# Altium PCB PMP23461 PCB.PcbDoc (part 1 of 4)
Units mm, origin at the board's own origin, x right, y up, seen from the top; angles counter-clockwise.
Board outline 240.04 x 159.92 mm, 6 copper layers (Layer 1, Layer 2, Layer 3, Layer 4, Layer 5, Layer 6), stack 2.017 mm thick; 241 components, 120 nets, 654 pads, 744 vias.
Unrouted connection lines stored in the file: 3.
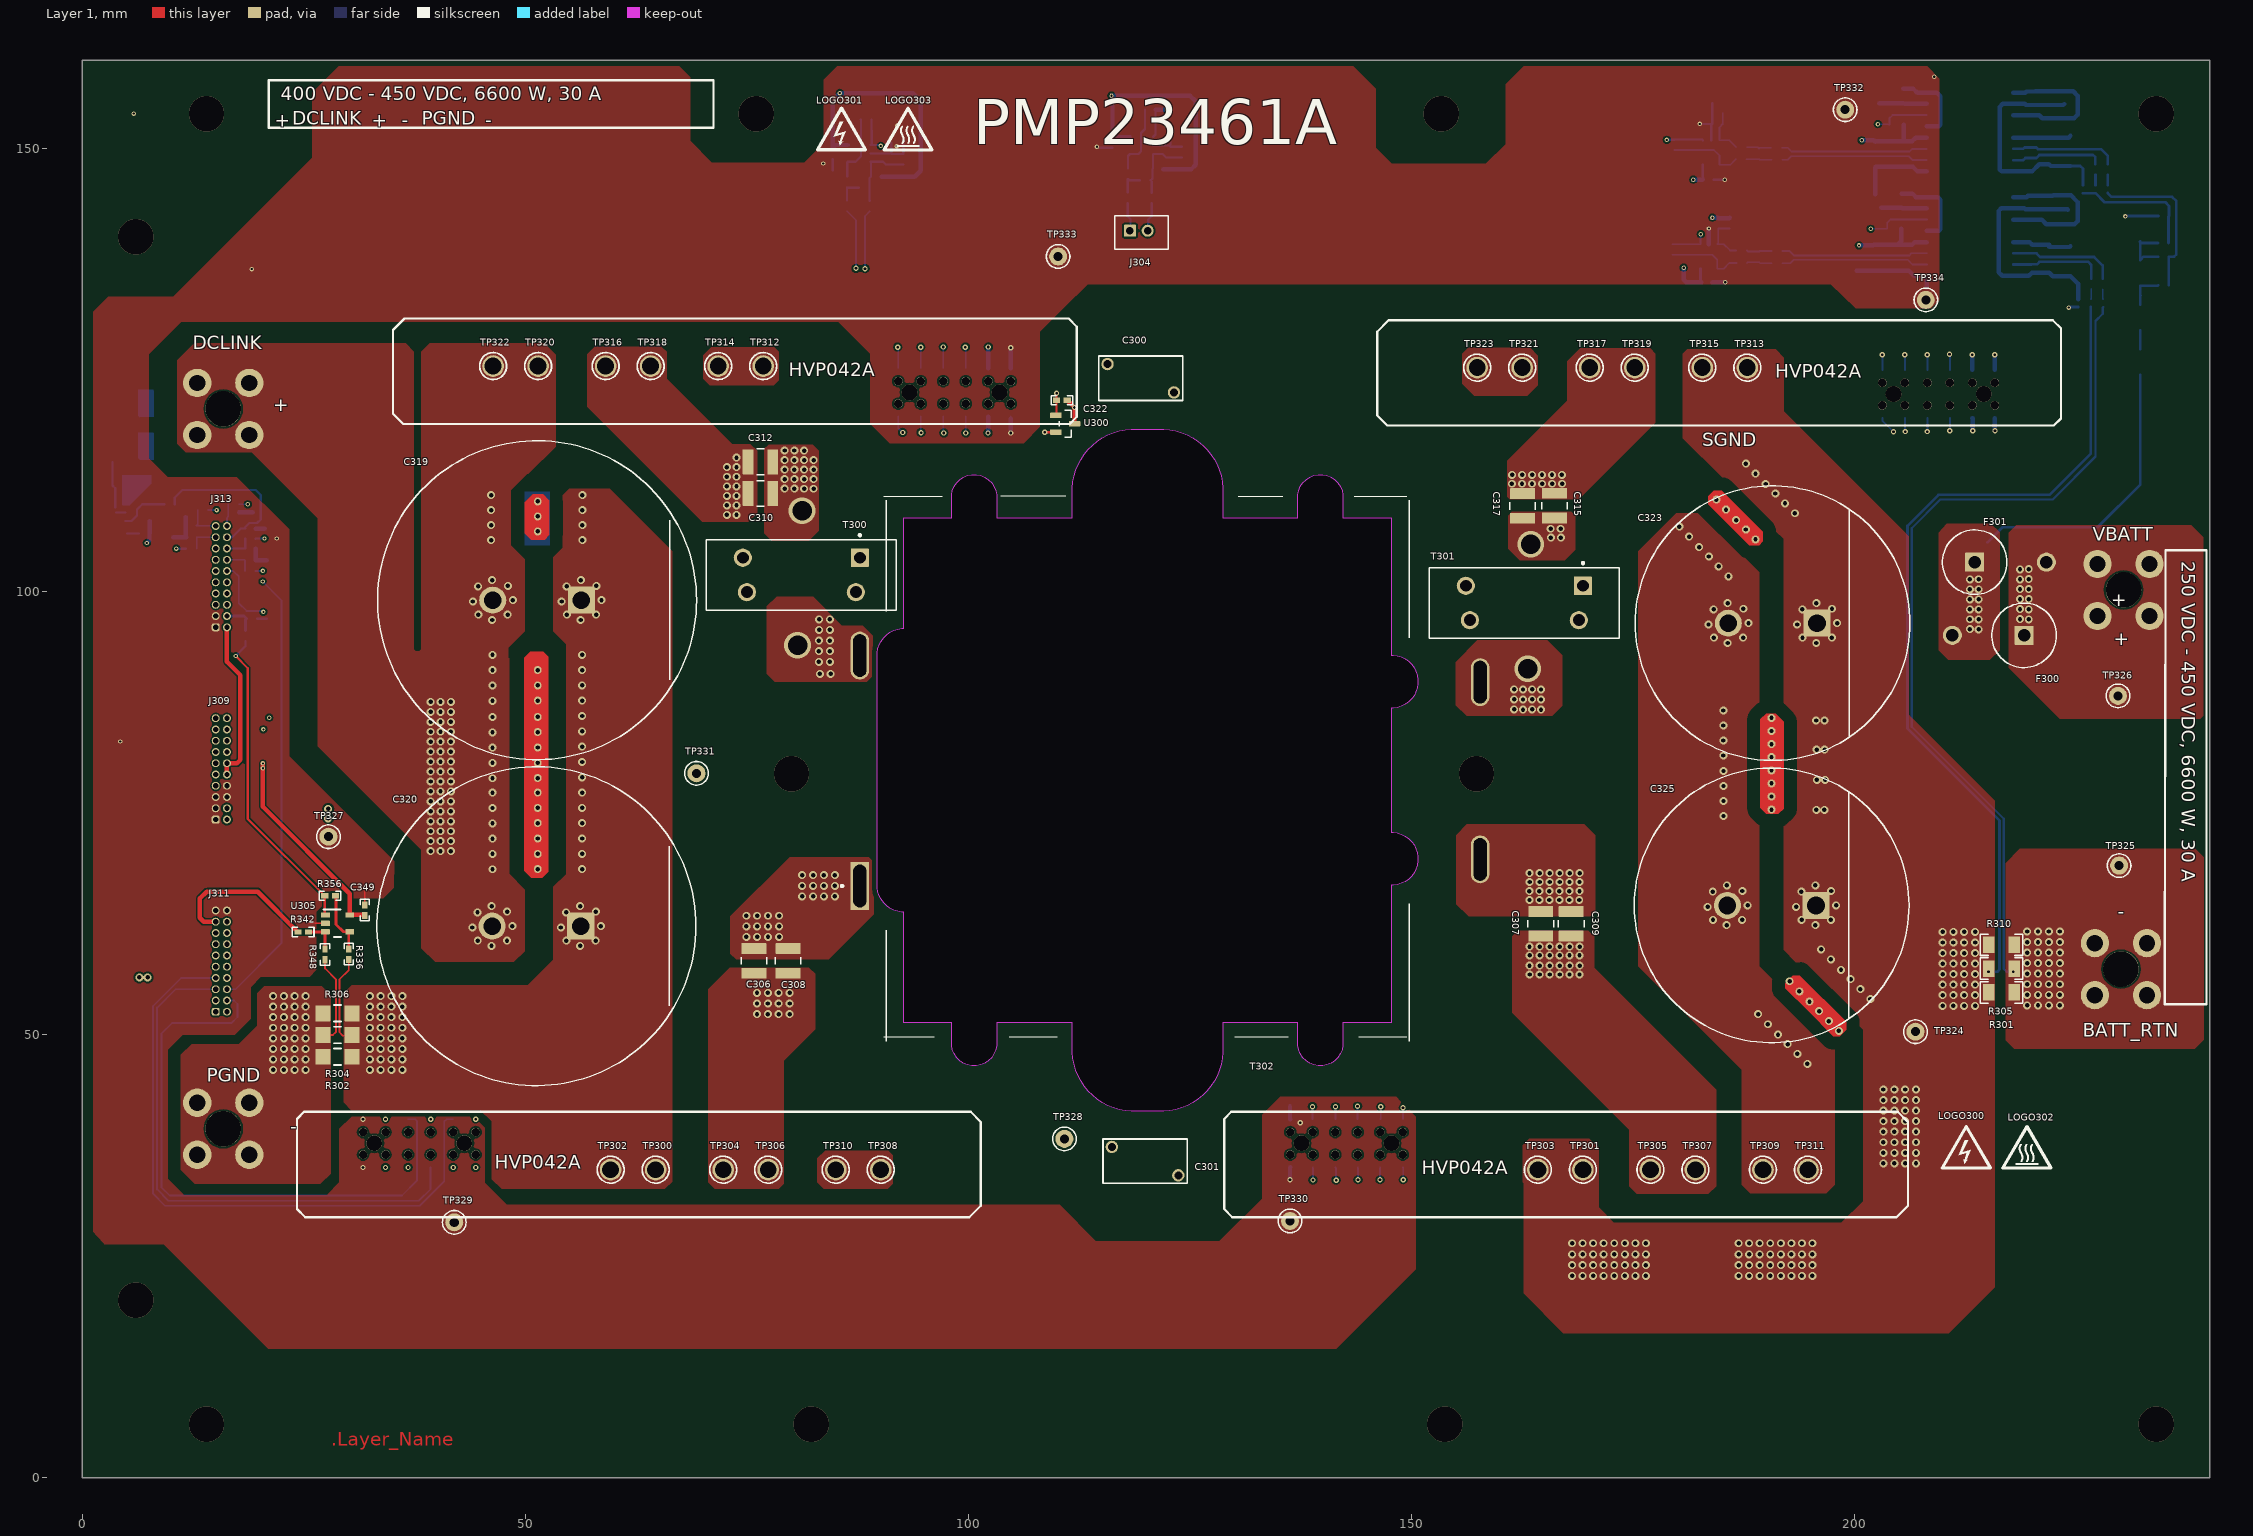
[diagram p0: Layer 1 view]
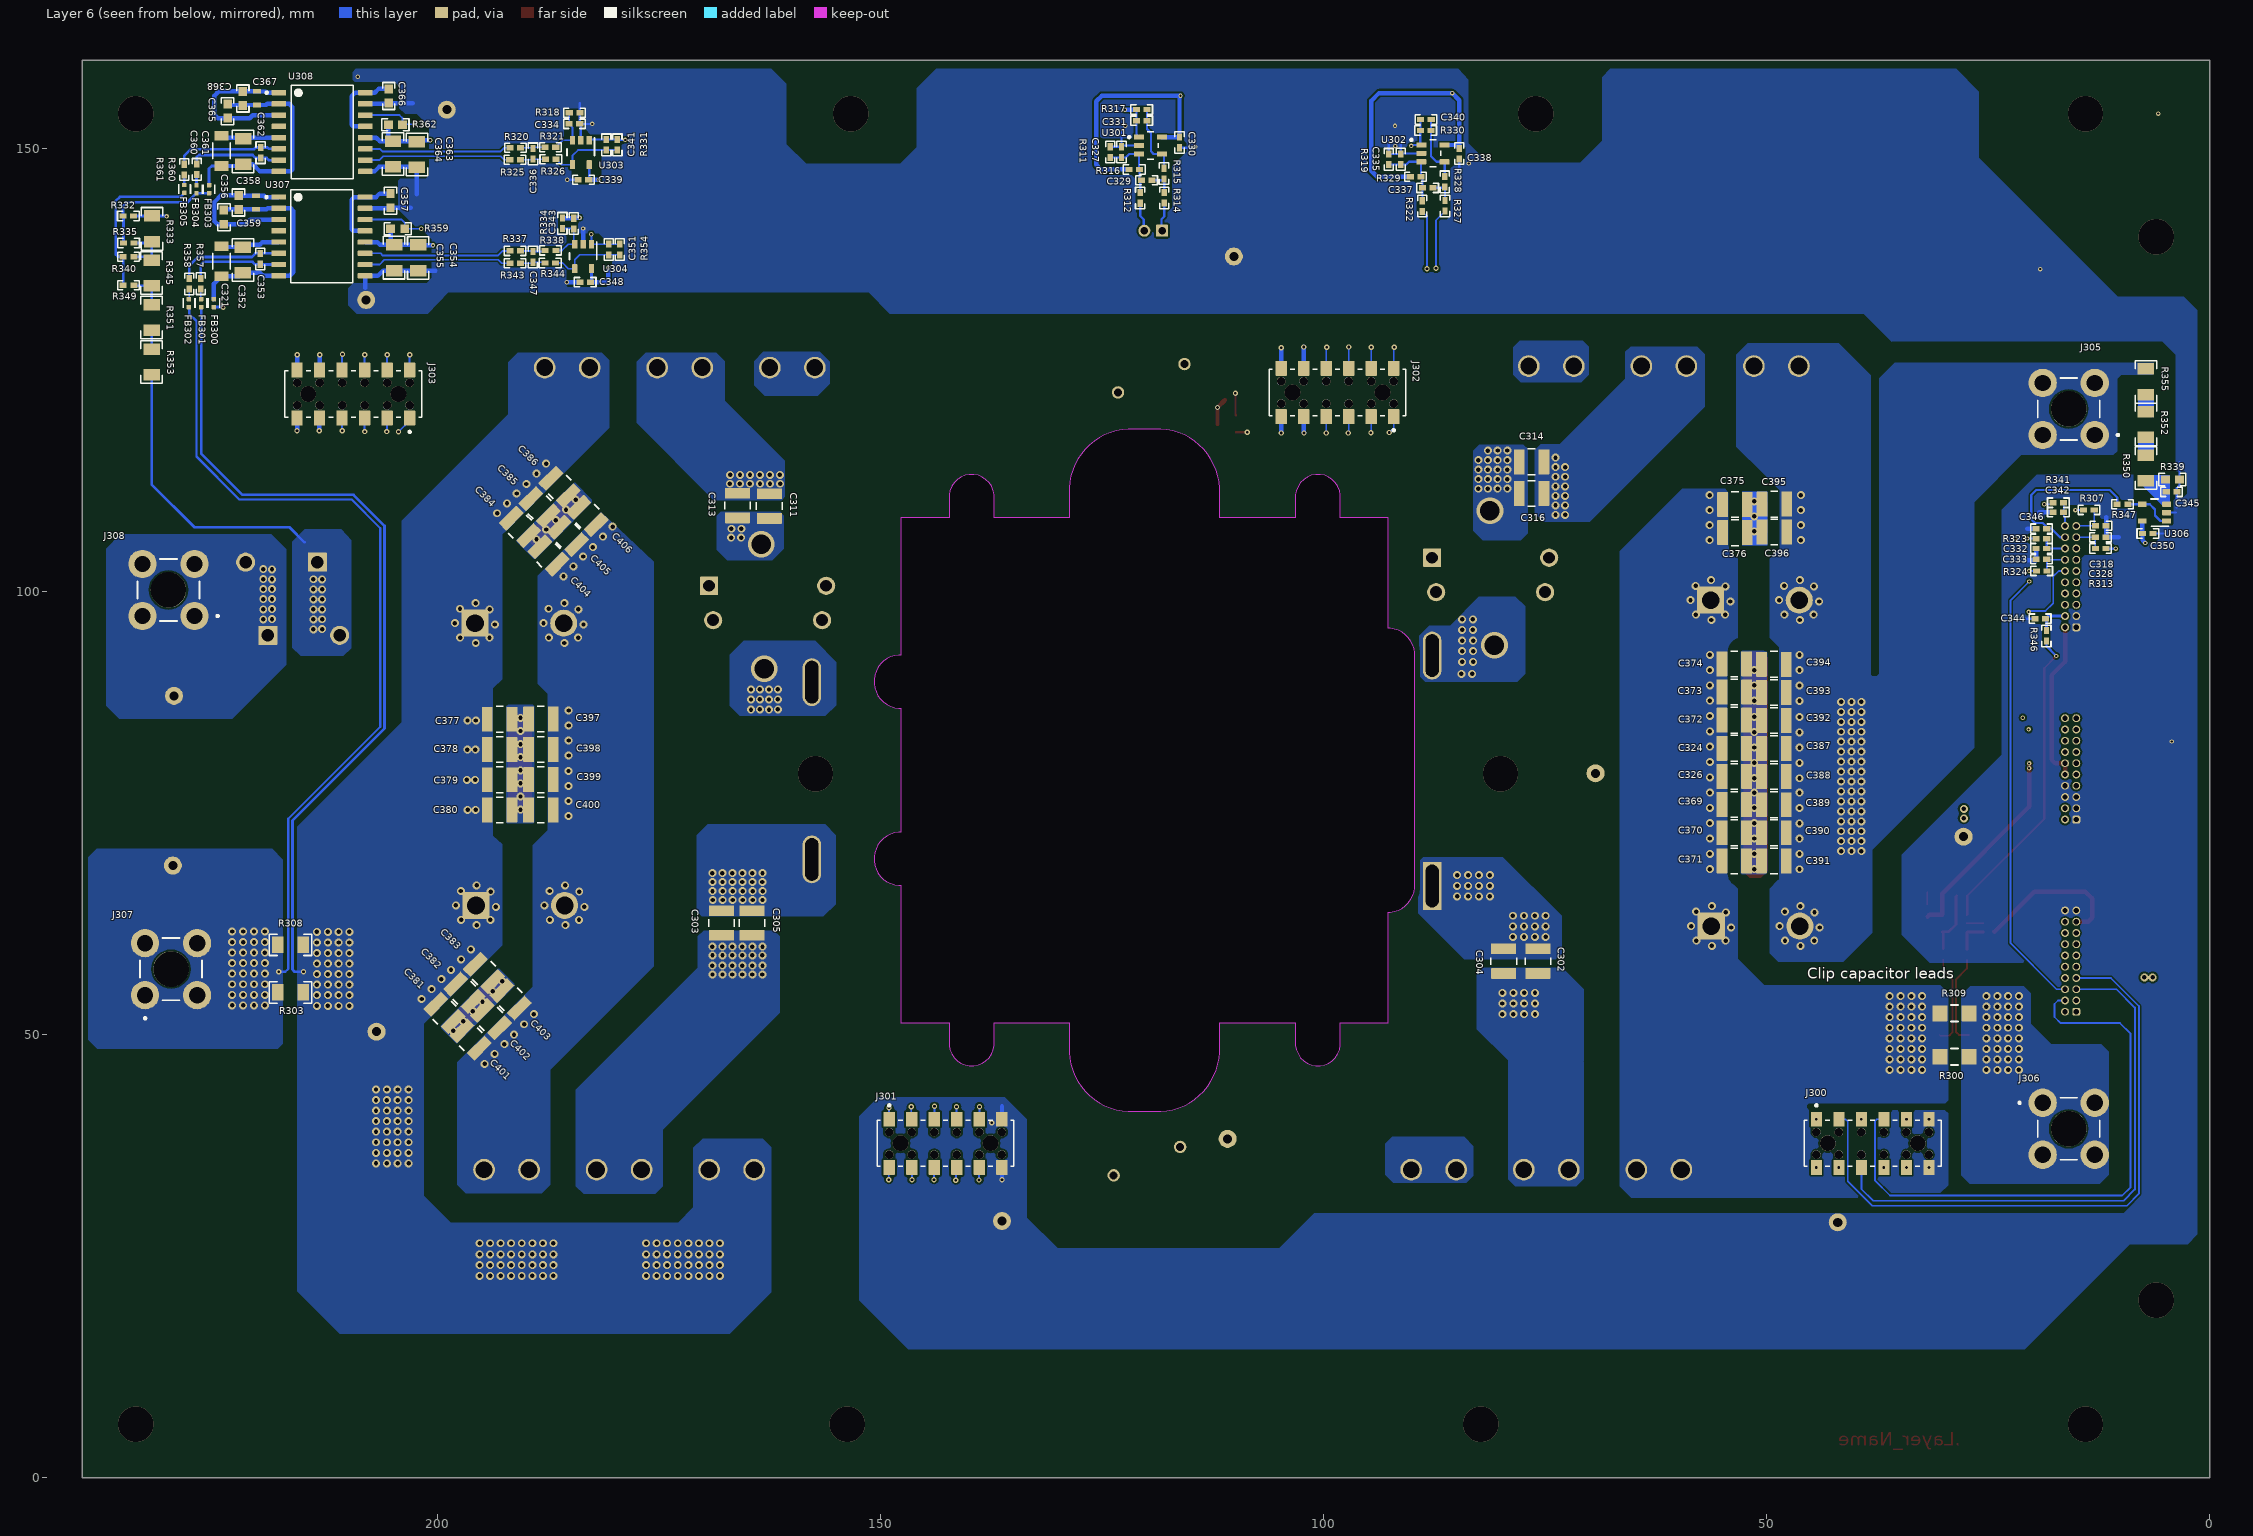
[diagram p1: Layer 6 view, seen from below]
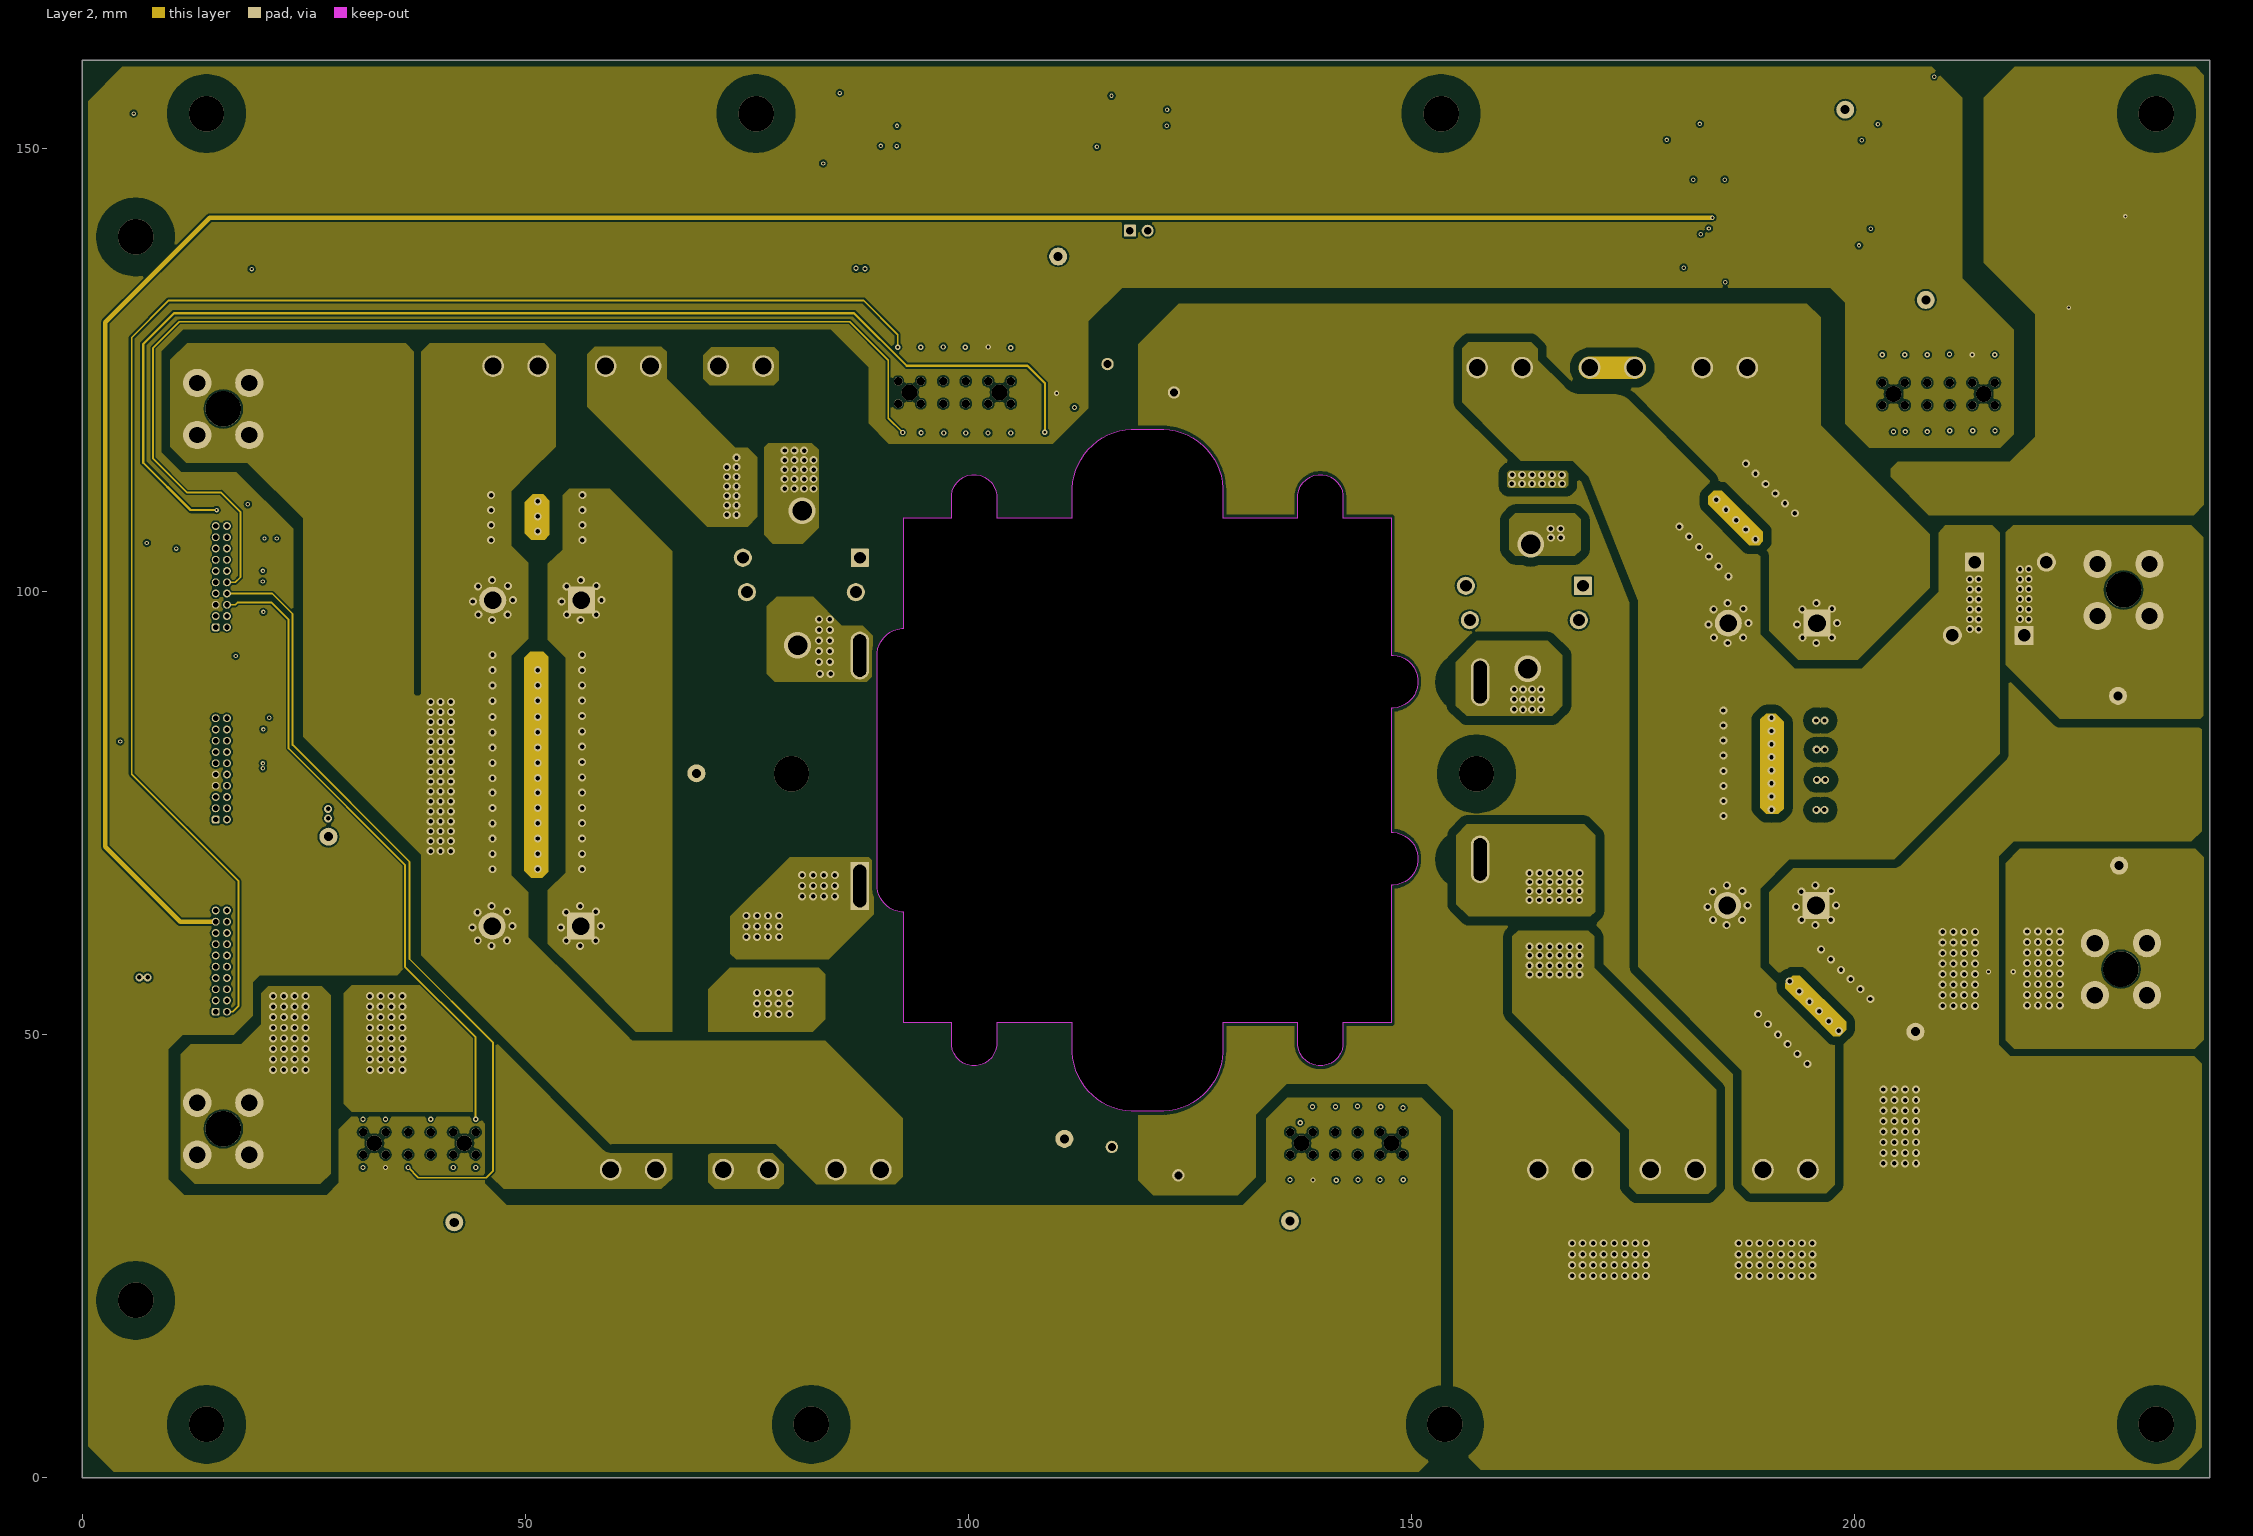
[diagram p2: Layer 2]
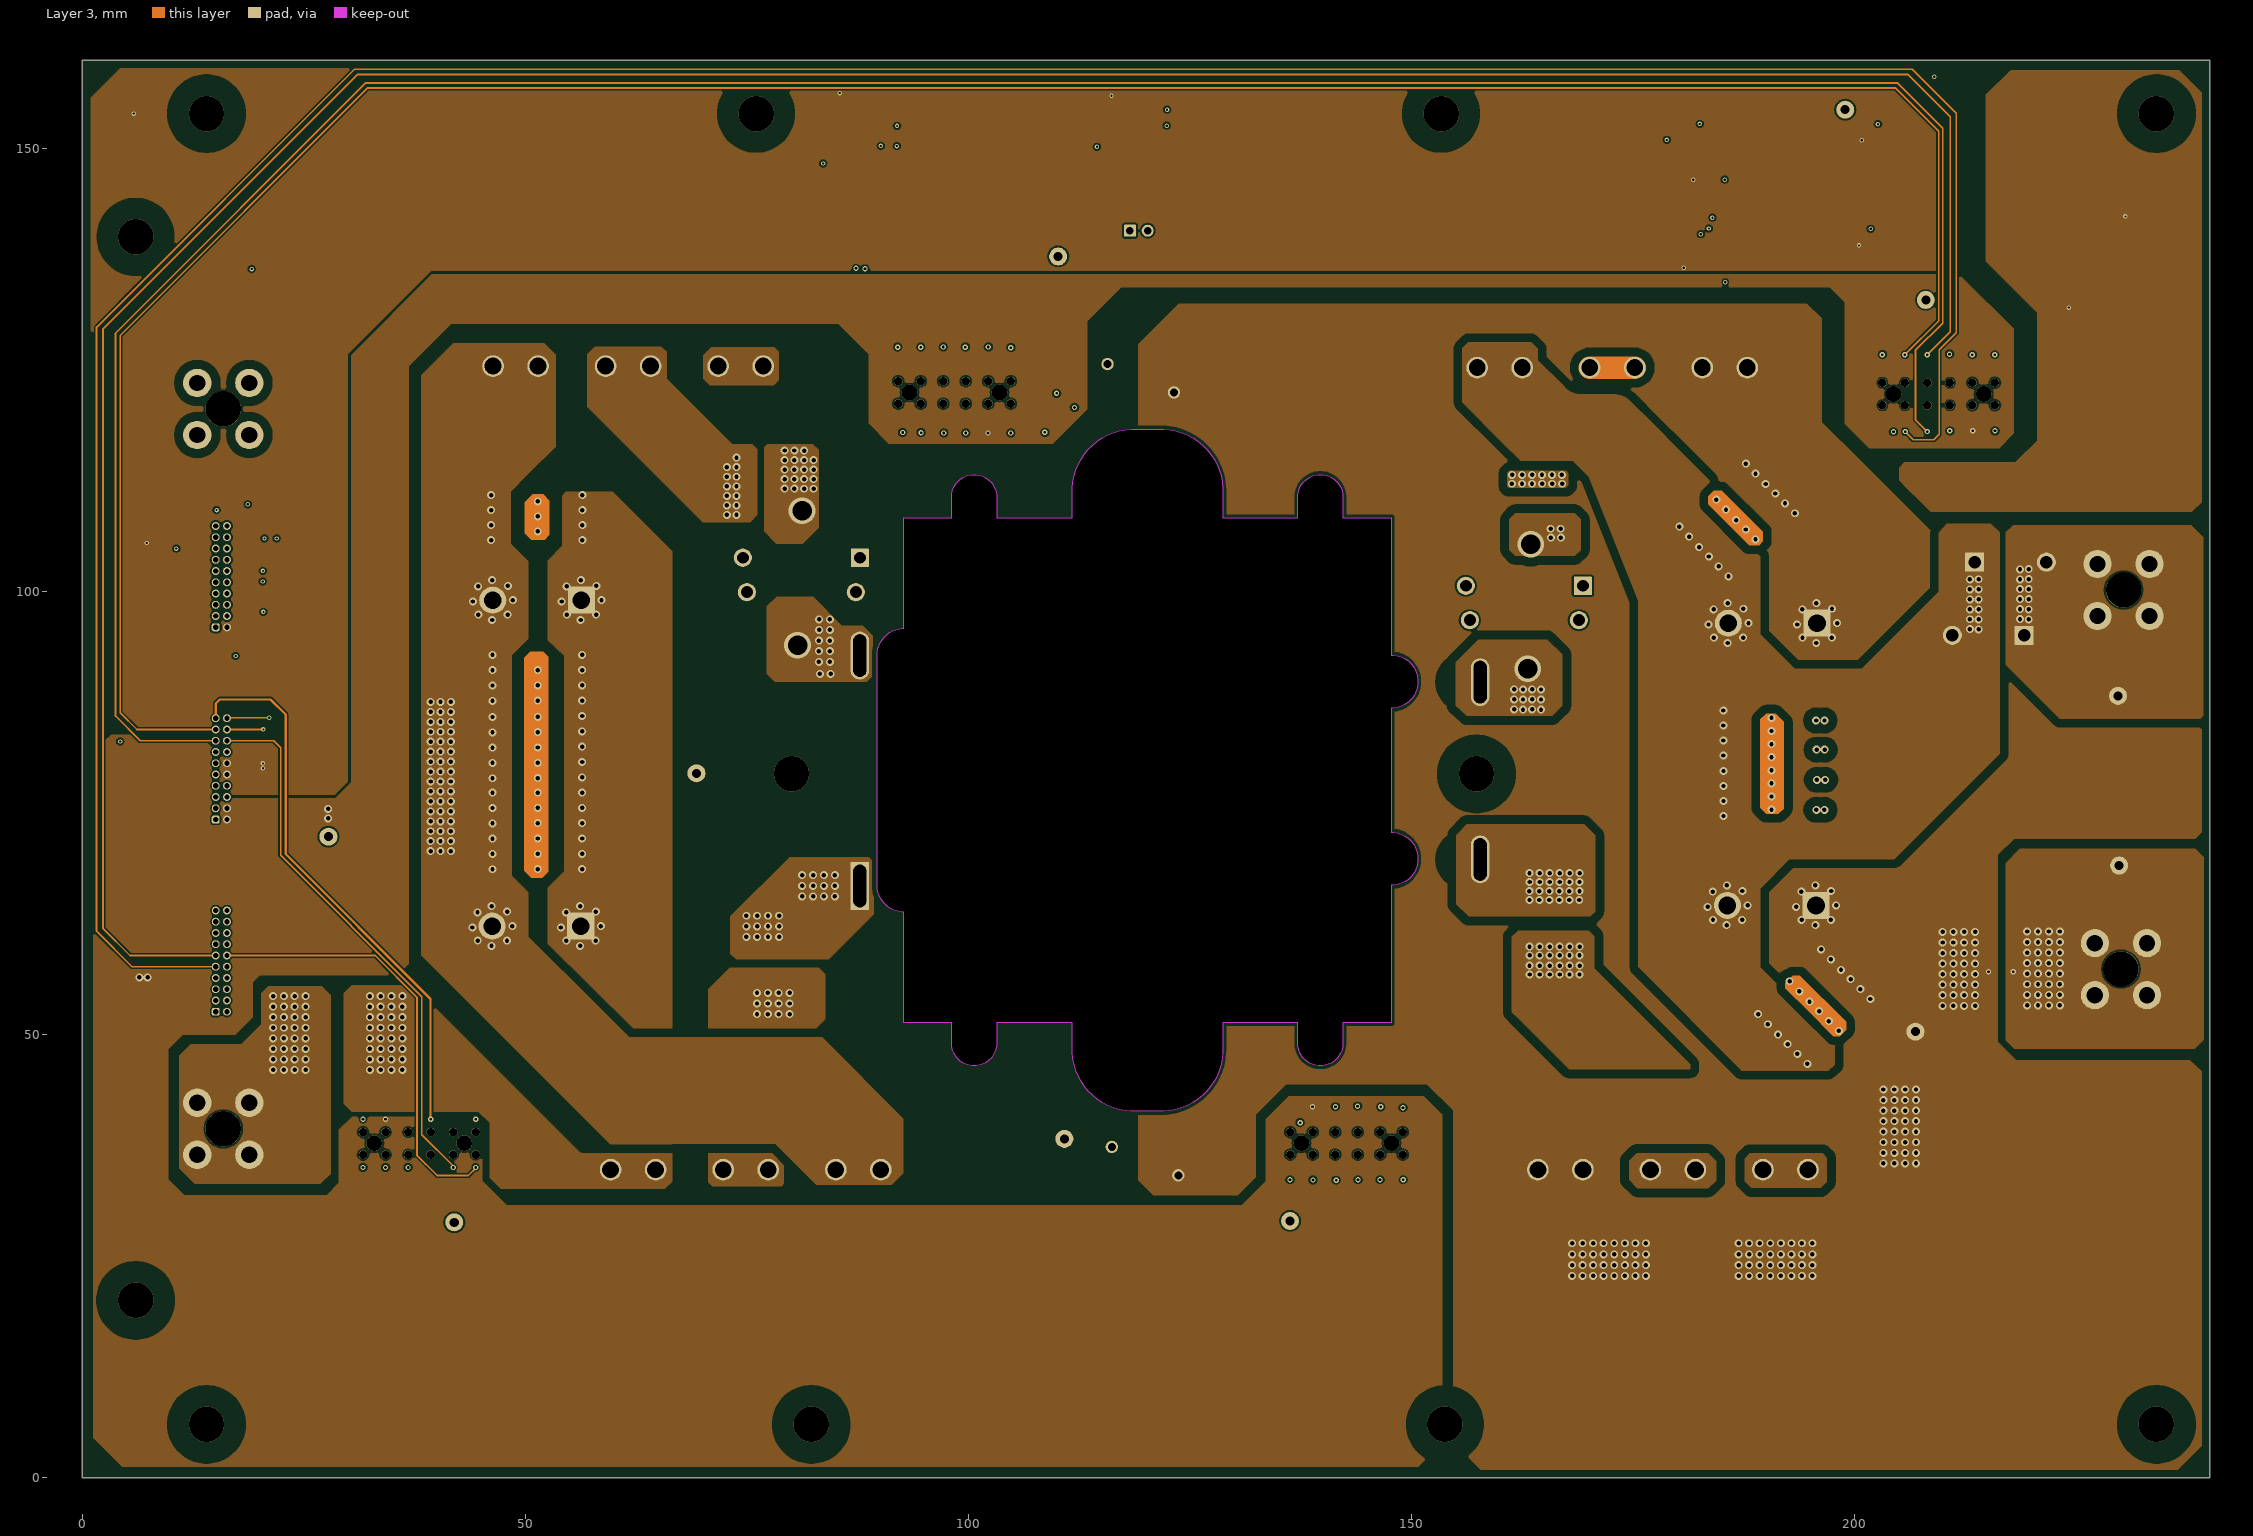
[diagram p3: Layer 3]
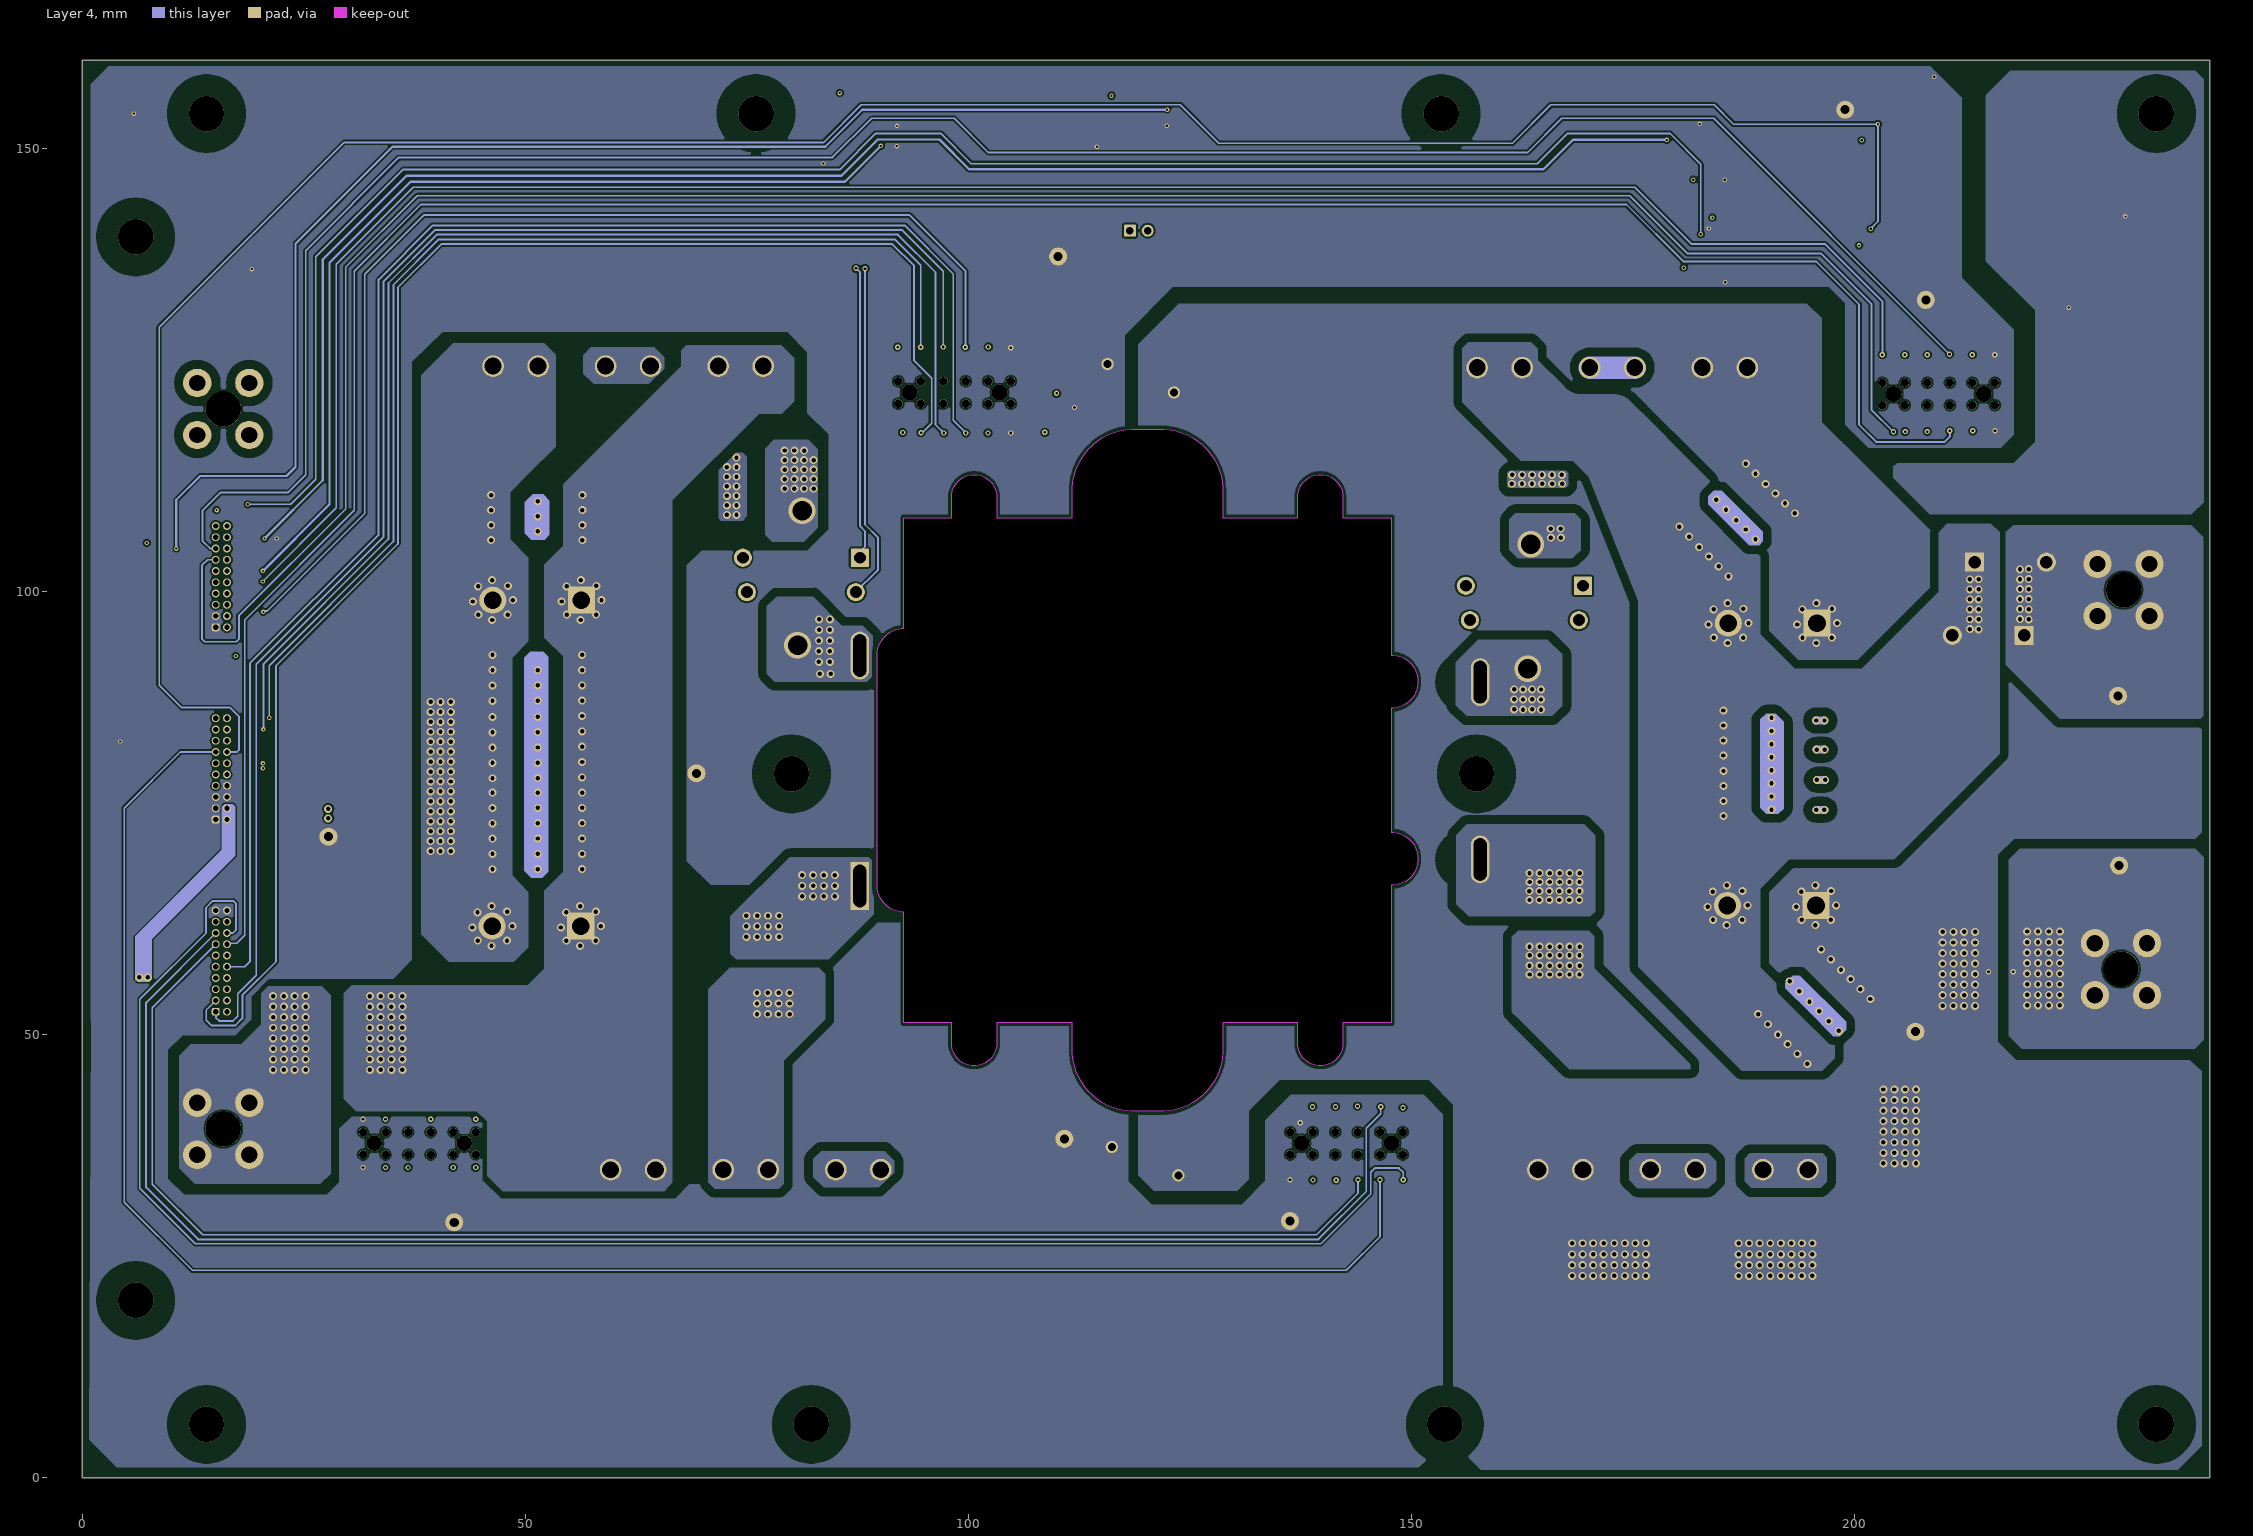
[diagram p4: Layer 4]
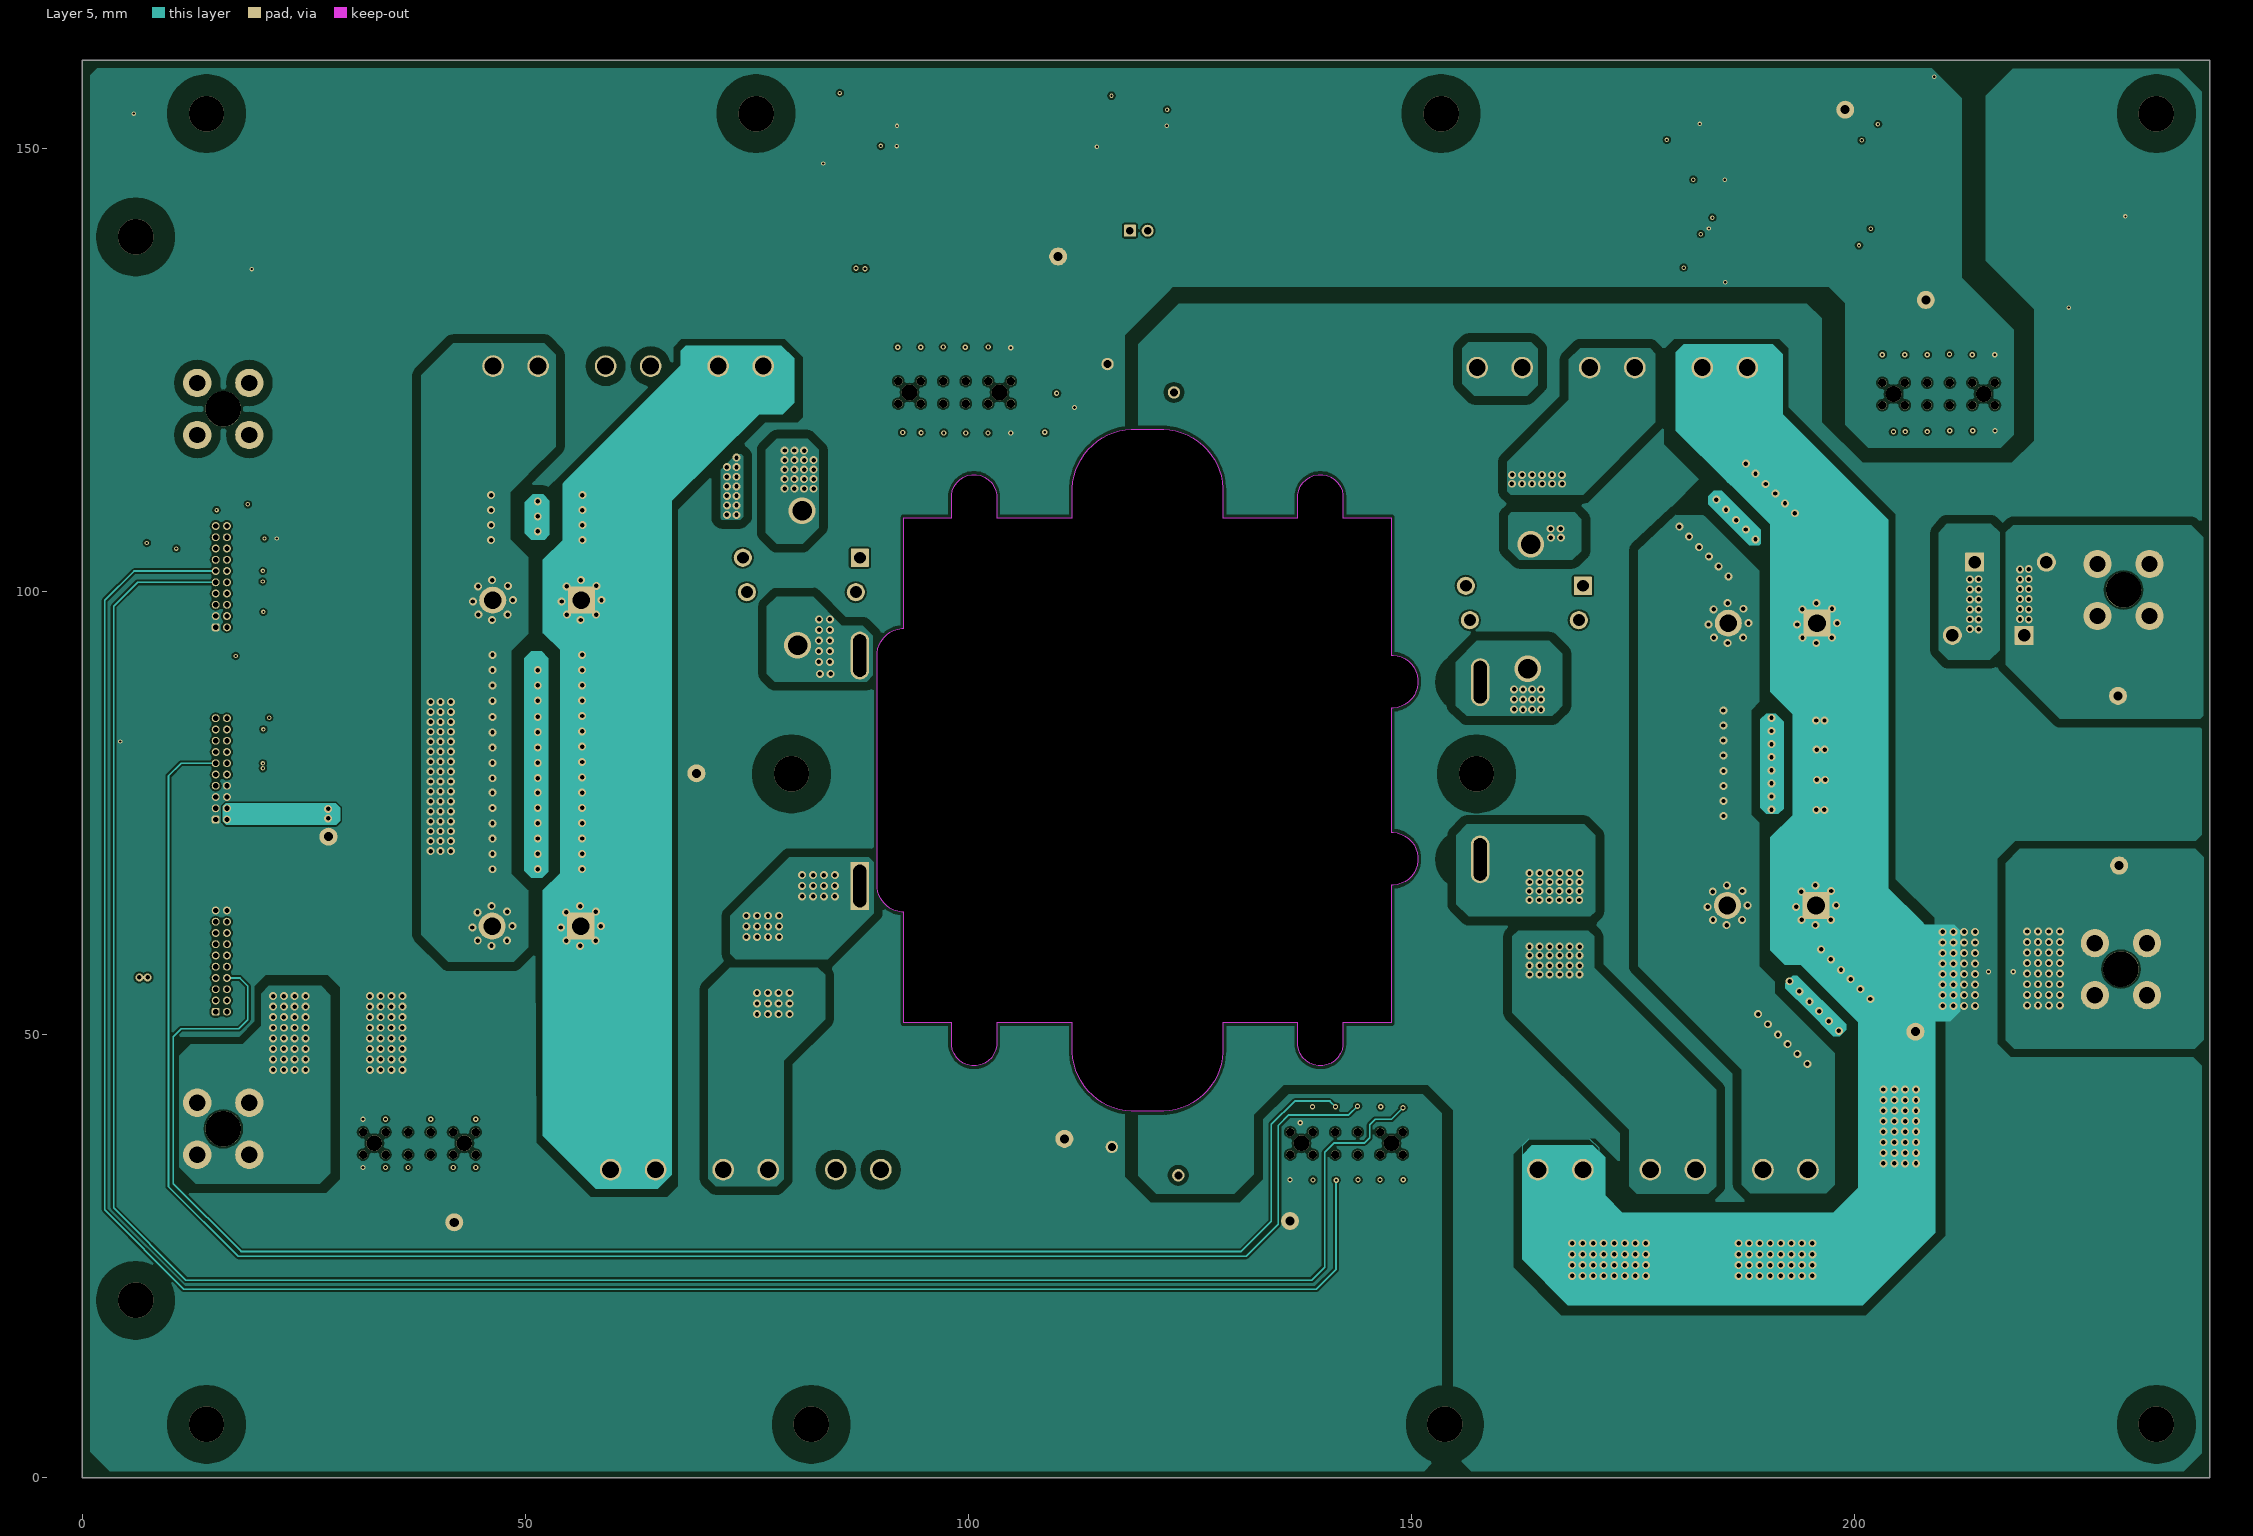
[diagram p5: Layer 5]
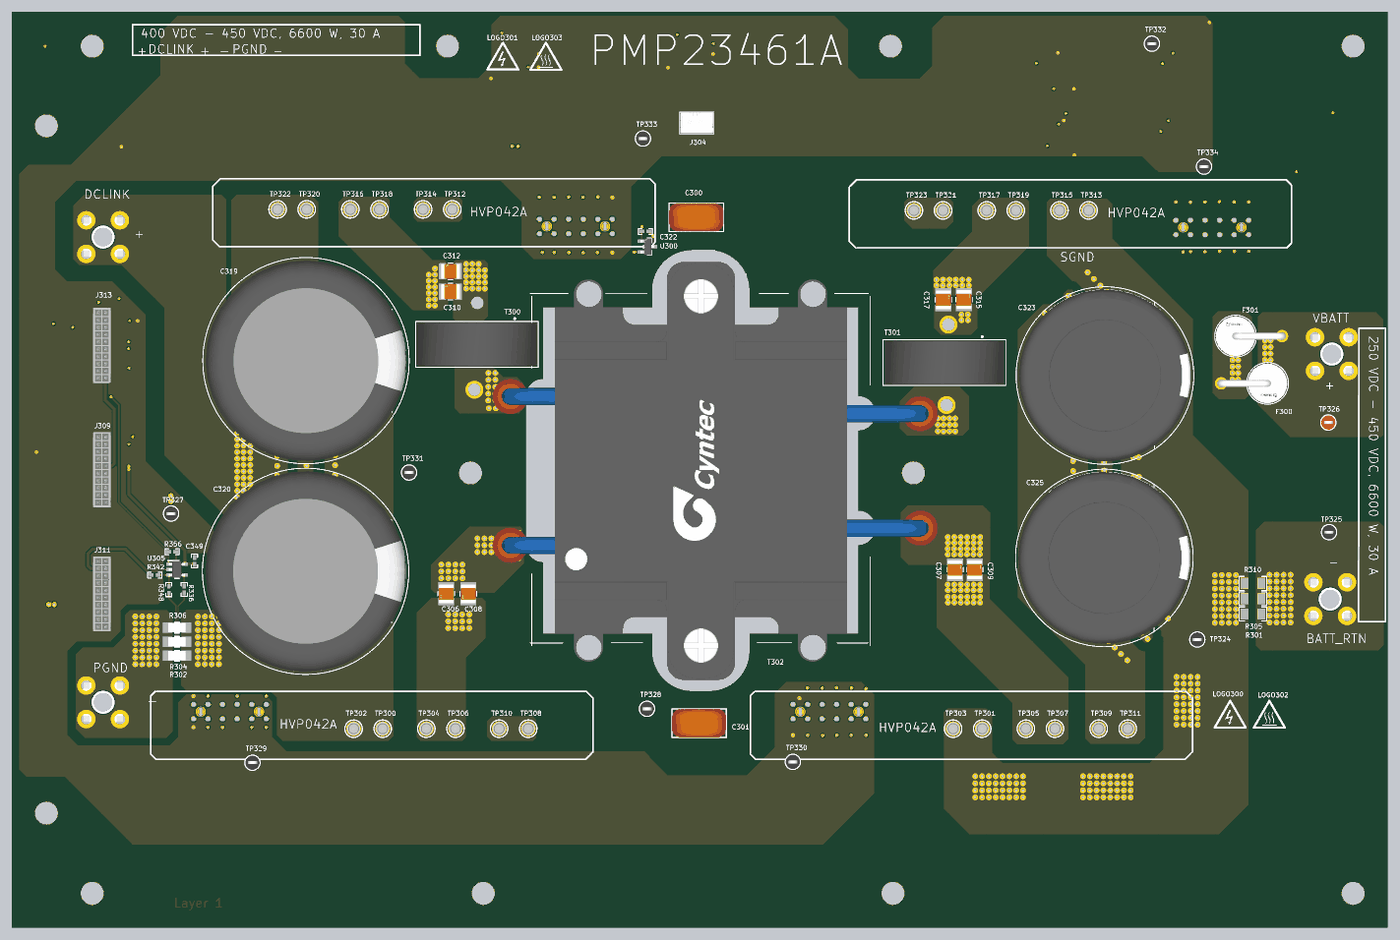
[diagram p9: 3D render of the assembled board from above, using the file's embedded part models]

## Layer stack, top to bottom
Top Solder: solder mask 0.0102, Solder Resist, Dk 3.5
Layer 1: signal copper 0.061
Dielectric 1: prepreg 0.381, FR-4, Dk 4.2
Layer 2: signal copper 0.061
Dielectric 2: core 0.254, FR-4, Dk 4.2
Layer 3: signal copper 0.061
Dielectric 3: prepreg 0.381, FR-4, Dk 4.2
Layer 4: signal copper 0.061
Dielectric 4: core 0.254, FR-4, Dk 4.2
Layer 5: signal copper 0.061
Dielectric 5: prepreg 0.381, FR-4, Dk 4.2
Layer 6: signal copper 0.061
Bottom Solder: solder mask 0.0102, Solder Resist, Dk 3.5

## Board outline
0,0 0,159.918 240.039,159.918 240.039,0
cut-out: 92.696,51.319 92.696,63.819 92.46,63.819 91.994,63.893 91.545,64.039 91.124,64.253 90.742,64.531 90.408,64.865 90.131,65.247 89.916,65.667 89.77,66.116 89.696,66.583 89.696,70.228 89.696,89.38 89.696,93.055 89.77,93.521 89.916,93.971 90.131,94.391 90.408,94.773 90.742,95.107 91.124,95.385 91.545,95.599 91.994,95.745 92.46,95.819 92.696,95.819 92.696,108.319 98.041,108.319 98.073,108.329 98.073,110.891 98.171,111.381 98.362,111.844 98.64,112.26 98.994,112.613 99.41,112.891 99.872,113.083 100.363,113.18 100.863,113.18 101.354,113.083 101.816,112.891 102.232,112.613 102.586,112.26 102.864,111.844 103.055,111.381 103.153,110.891 103.153,108.332 103.172,108.319 111.696,108.319 111.696,111.663 111.764,112.347 111.898,113.022 112.098,113.68 112.361,114.315 112.685,114.922 113.067,115.494 113.503,116.026 113.99,116.512 114.521,116.948 115.093,117.33 115.7,117.655 116.335,117.918 116.993,118.117 117.668,118.252 118.353,118.319 118.696,118.319 121.696,118.319 122.04,118.319 122.725,118.252 123.399,118.117 124.057,117.918 124.693,117.655 125.299,117.33 125.871,116.948 126.403,116.512 126.889,116.026 127.326,115.494 127.708,114.922 128.032,114.315 128.295,113.68 128.495,113.022 128.629,112.347 128.696,111.663 128.696,111.319 128.696,108.319 137.157,108.319 137.16,110.891 137.257,111.381 137.449,111.844 137.727,112.26 138.081,112.613 138.497,112.891 138.959,113.083 139.45,113.18 139.95,113.18 140.441,113.083 140.903,112.891 141.319,112.613 141.673,112.26 141.951,111.844 142.142,111.381 142.24,110.891 142.24,108.332 142.262,108.319 147.696,108.319 147.696,92.819 147.933,92.819 148.399,92.745 148.848,92.599 149.269,92.385 149.651,92.107 149.985,91.773 150.262,91.391 150.477,90.971 150.623,90.522 150.696,90.055 150.696,89.583 150.623,89.116 150.477,88.667 150.262,88.247 149.985,87.865 149.651,87.531 149.269,87.253 148.848,87.039 148.399,86.893 147.933,86.819 147.696,86.819 147.696,72.819 147.933,72.819 148.399,72.745 148.848,72.599 149.269,72.385 149.651,72.107 149.985,71.773 150.262,71.391 150.477,70.971 150.623,70.521 150.696,70.055 150.696,69.583 150.623,69.116 150.477,68.667 150.262,68.247 149.985,67.865 149.651,67.531 149.269,67.253 148.848,67.039 148.399,66.893 147.933,66.819 147.696,66.819 147.696,51.319 142.24,51.319 142.24,48.765 142.142,48.275 141.951,47.812 141.673,47.396 141.319,47.043 140.903,46.765 140.441,46.573 139.95,46.476 139.45,46.476 138.959,46.573 138.497,46.765 138.081,47.043 137.727,47.396 137.449,47.812 137.257,48.275 137.16,48.765 137.16,51.319 128.696,51.319 128.696,48.319 128.696,47.975 128.629,47.291 128.495,46.616 128.295,45.958 128.032,45.323 127.708,44.716 127.326,44.144 126.889,43.612 126.403,43.126 125.871,42.69 125.299,42.308 124.693,41.983 124.057,41.72 123.399,41.521 122.725,41.386 122.04,41.319 118.353,41.319 117.668,41.386 116.993,41.521 116.335,41.72 115.7,41.983 115.093,42.308 114.521,42.69 113.99,43.126 113.503,43.612 113.067,44.144 112.685,44.716 112.361,45.323 112.098,45.958 111.898,46.616 111.764,47.291 111.696,47.975 111.696,51.319 103.153,51.319 103.153,48.765 103.055,48.275 102.864,47.812 102.586,47.396 102.232,47.043 101.816,46.765 101.354,46.573 100.863,46.476 100.363,46.476 99.872,46.573 99.41,46.765 98.994,47.043 98.64,47.396 98.362,47.812 98.171,48.275 98.073,48.765 98.073,51.319

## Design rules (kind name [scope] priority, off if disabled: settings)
AcuteAngle [All] p1: minimum=4.50000000000000E+0001 checktracksonly=FALSE
AssemblyTestPointUsage [All] p1: valid=2
BoardOutlineClearance BoardOutlineClearance_Silk [(OnLayer('Top Overlay') or OnLayer('Bottom Overlay') or OnTopSilkscreen or OnBottomSilkscreen)] p1: gap=0 ignorepadtopadclearanceinfootprint=FALSE
BoardOutlineClearance BoardOutlineClearance_MountingHoles [OnCopper and InComponentClass('Mounting Holes')] p2: gap=1 ignorepadtopadclearanceinfootprint=FALSE
BoardOutlineClearance BoardOutlineClearance_Poly [OnCopper and IsPoly] p3: gap=0.635 ignorepadtopadclearanceinfootprint=FALSE
BoardOutlineClearance [OnCopper And Not InComponentClass('Logo') and not InComponentClass('FiducialMark') and not InRegion(1000,500,4000,800)] p4: gap=0.4 ignorepadtopadclearanceinfootprint=FALSE
Clearance Clearance_Earth_Outside [(OnLayer('Layer 1') Or OnLayer('Layer 8')) And InNet('EARTH')] p1: gap=4.14 ignorepadtopadclearanceinfootprint=TRUE
Clearance Clearance_Earth_Inside [InNet('EARTH')] p2: gap=1.6 ignorepadtopadclearanceinfootprint=TRUE
Clearance Clearance_HV_Outside [InNetClass('HV') And (OnTopLayer Or OnBottomLayer Or IsVia Or IsPad) And (Not Keepout) And InAnyNet vs (Not InNetClass('HV')) And (OnTopLayer Or OnBottomLayer Or IsVia Or IsPad) And (Not Keepout) And InAnyNet] p3: gap=1.524 ignorepadtopadclearanceinfootprint=TRUE
Clearance Clearance_HV_Inside [InNetClass('HV') vs Not InNetClass('HV') And InAnyNet] p4: gap=1 ignorepadtopadclearanceinfootprint=TRUE
Clearance Clearance_HV_SW_Outside [InNetClass('HV_SW') And (OnTopLayer Or OnBottomLayer Or IsVia Or IsPad) And (Not Keepout) And InAnyNet vs (Not InNetClass('HV_SW')) And (OnTopLayer Or OnBottomLayer Or IsVia Or IsPad) And (Not Keepout) And InAnyNet] p5: gap=1.524 ignorepadtopadclearanceinfootprint=TRUE
Clearance Clearance_PS_Outside [InNetClass('Secondary') And (OnTopLayer Or OnBottomLayer Or IsVia Or IsPad) And (Not Keepout) And InAnyNet vs (Not InNetClass('Secondary')) And (OnTopLayer Or OnBottomLayer Or IsVia Or IsPad) And (Not Keepout) And InAnyNet] p6: gap=1.524 ignorepadtopadclearanceinfootprint=TRUE
Clearance Clearance_HV_SW_Inside [InNetClass('HV_SW') vs Not InNetClass('HV_SW') And InAnyNet] p7: gap=1 ignorepadtopadclearanceinfootprint=TRUE
Clearance Clearance_PS_Inside [InNetClass('Secondary') vs Not InNetClass('Secondary') And InAnyNet] p8: gap=1 ignorepadtopadclearanceinfootprint=TRUE
Clearance Clearance_Keepouts [((IsTrack Or IsArc) And Not InPoly) And IsFree and IsKeepOut vs ((IsTrack Or IsArc) And Not InPoly) And IsFree and IsKeepOut] p9: gap=0 ignorepadtopadclearanceinfootprint=FALSE
Clearance Clearance_Poly [InPolygon] p10: gap=0.2 ignorepadtopadclearanceinfootprint=TRUE
Clearance Clearance_FiducialMark [IsKeepOut and InComponentClass('FiducialMark') vs IsPad and InComponentClass('FiducialMark')] p11: gap=0 ignorepadtopadclearanceinfootprint=FALSE
Clearance [All] p12: gap=0.2 ignorepadtopadclearanceinfootprint=TRUE
ComponentClearance PFC_Inductor [InComponent('L18')] p1: gap=0 collisioncheckmode=3 verticalgap=0.254 showdistances=FALSE
ComponentClearance LC_Ind_XFMR [InComponent('T1') vs InComponent('L19')] p2: gap=0 collisioncheckmode=3 verticalgap=0 showdistances=FALSE
ComponentClearance LMG_Bottom_Clearance [HasFootprint('RQS0052A-MFG') vs Not HasFootprint('RQS0052A-MFG')] p3: gap=2 collisioncheckmode=3 verticalgap=0 showdistances=FALSE
ComponentClearance ComponentClearance_Sec_RogCoil [InComponent('T1') vs InComponent('T3')] p4: gap=0 collisioncheckmode=3 verticalgap=0 showdistances=FALSE
ComponentClearance ComponentClearance_MountingHoles_FiducialMarks [InComponentClass('Mounting Holes') vs InComponentClass('FiducialMark')] p5: gap=1.27 collisioncheckmode=3 verticalgap=0.254 showdistances=FALSE
ComponentClearance ComponentClearance_Shunt [InComponentClass('Header') vs InComponentClass('Shunt')] p6: gap=0 collisioncheckmode=3 verticalgap=0 showdistances=FALSE
ComponentClearance ComponentClearance_Logo [InComponentClass('Logo')] p7: gap=1.27 collisioncheckmode=3 verticalgap=0.254 showdistances=FALSE
ComponentClearance ComponentClearance_ScrewToNut [(HasFootprint('NY PMS 440 0025 PH')) vs (HasFootprint('Keystone_1902C'))] p8: gap=0.127 collisioncheckmode=3 verticalgap=0.254 showdistances=FALSE
ComponentClearance ComponentClearance_MountingHoles [InComponentClass('Mounting Holes')] p9: gap=6.35 collisioncheckmode=3 verticalgap=2540 showdistances=FALSE
ComponentClearance ComponentClearance_SmallPassives [HasFootprint('0201*') or HasFootprint('0402*') or HasFootprint('0508') or HasFootprint('0603*') or HasFootprint('0612') or HasFootprint('0805*') or HasFootprint('0815*') or HasFootprint('0830*') or HasFootprint('1206*') or HasFootprint('1210*') or HasFootprint('1808*') or HasFootprint('1812*') or HasFootprint('1825*') or HasFootprint('2010*') or HasFootprint('2220*') or HasFootprint('2225*') or HasFootprint('2512*') or HasFootprint('2728*') or HasFootprint('3518*') vs HasFootprint('0201*') or HasFootprint('0402*') or HasFootprint('0508') or HasFootprint('0603*') or HasFootprint('0612') or HasFootprint('0805*') or HasFootprint('0815*') or HasFootprint('0830*') or HasFootprint('1206*') or HasFootprint('1210*') or HasFootprint('1808*') or HasFootprint('1812*') or HasFootprint('1825*') or HasFootprint('2010*') or HasFootprint('2220*') or HasFootprint('2225*') or HasFootprint('2512*') or HasFootprint('2728*') or HasFootprint('3518*')] p10: gap=0.38 collisioncheckmode=3 verticalgap=0.254 showdistances=FALSE
ComponentClearance ComponentClearance_THtoSMT [IsThruComponent vs IsSMTComponent] p11: gap=1.016 collisioncheckmode=3 verticalgap=0.762 showdistances=FALSE
ComponentClearance ComponentClearance_THtoTH [IsThruComponent vs IsThruComponent] p12: gap=0.762 collisioncheckmode=3 verticalgap=0.762 showdistances=FALSE
ComponentClearance [All] p13: gap=0.5 collisioncheckmode=3 verticalgap=0.254 showdistances=FALSE
DiffPairsRouting [All] p1: maxlimit=2.54 minlimit=0.254 mostfreqgap=0.254 toplayer_minwidth=0.381 toplayer_maxwidth=0.381 toplayer_prefwidth=0.381 midlayer3_minwidth=0.381 midlayer3_maxwidth=0.381 midlayer3_prefwidth=0.381 midlayer4_minwidth=0.381 midlayer4_maxwidth=0.381 midlayer4_prefwidth=0.381 midlayer5_minwidth=0.381 midlayer5_maxwidth=0.381 midlayer5_prefwidth=0.381 midlayer6_minwidth=0.381 midlayer6_maxwidth=0.381 midlayer6_prefwidth=0.381 bottomlayer_minwidth=0.381 bottomlayer_maxwidth=0.381 bottomlayer_prefwidth=0.381 substack1={36F540E3-592C-4459-9B98-FC5FBF0C6E90} toplayer_{36f540e3-592c-4459-9b98-fc5fbf0c6e90}_minwidth=0.381 toplayer_{36f540e3-592c-4459-9b98-fc5fbf0c6e90}_maxwidth=0.381 toplayer_{36f540e3-592c-4459-9b98-fc5fbf0c6e90}_prefwidth=0.381 midlayer3_{36f540e3-592c-4459-9b98-fc5fbf0c6e90}_minwidth=0.381 midlayer3_{36f540e3-592c-4459-9b98-fc5fbf0c6e90}_maxwidth=0.381 midlayer3_{36f540e3-592c-4459-9b98-fc5fbf0c6e90}_prefwidth=0.381 midlayer4_{36f540e3-592c-4459-9b98-fc5fbf0c6e90}_minwidth=0.381 midlayer4_{36f540e3-592c-4459-9b98-fc5fbf0c6e90}_maxwidth=0.381 midlayer4_{36f540e3-592c-4459-9b98-fc5fbf0c6e90}_prefwidth=0.381 midlayer5_{36f540e3-592c-4459-9b98-fc5fbf0c6e90}_minwidth=0.381 midlayer5_{36f540e3-592c-4459-9b98-fc5fbf0c6e90}_maxwidth=0.381 midlayer5_{36f540e3-592c-4459-9b98-fc5fbf0c6e90}_prefwidth=0.381 midlayer6_{36f540e3-592c-4459-9b98-fc5fbf0c6e90}_minwidth=0.381 midlayer6_{36f540e3-592c-4459-9b98-fc5fbf0c6e90}_maxwidth=0.381 midlayer6_{36f540e3-592c-4459-9b98-fc5fbf0c6e90}_prefwidth=0.381 bottomlayer_{36f540e3-592c-4459-9b98-fc5fbf0c6e90}_minwidth=0.381 bottomlayer_{36f540e3-592c-4459-9b98-fc5fbf0c6e90}_maxwidth=0.381 bottomlayer_{36f540e3-592c-4459-9b98-fc5fbf0c6e90}_prefwidth=0.381 maxuncoupledlength=25.4
FabricationTestPointUsage TestPointUsage [All] p1: valid=2 allowmultiple=FALSE
FabricationTestpoint Testpoint [All] p1: side=3 testpointundercomponent=TRUE minsize=1.016 maxsize=2.54 preferedsize=1.524 minholesize=0 maxholesize=1.016 preferedholesize=0.813 testpointgrid=0.025 allowsidetop=TRUE allowsidebottom=TRUE usegrid=TRUE gridtolerance=0
FanoutControl Fanout_LCC [IsLCC] p1: bgadir=Out bgaviamode=Centered fanoutstyle=Auto fanoutdirection=Alternating viagrid=0.025 // Fanout_LCC (Default Rule)
FanoutControl Fanout_BGA [IsBGA] p2: bgadir=Out bgaviamode=Centered fanoutstyle=Auto fanoutdirection=Alternating viagrid=0.025 // Fanout_BGA (Default Rule)
FanoutControl Fanout_Default [All] p4: bgadir=Out bgaviamode=Centered fanoutstyle=Auto fanoutdirection=Alternating viagrid=0.025 // Fanout_Default (Default Rule)
FanoutControl Fanout_Small [(CompPinCount < 5)] p5: bgadir=Out bgaviamode=Centered fanoutstyle=Auto fanoutdirection=OutThenIn viagrid=0.025 // Fanout_Small (Default Rule)
Height [All] p1: minheight=0 maxheight=50 prefheight=50
HoleSize [All] p1: absolutevalues=TRUE maxlimit=6.375 minlimit=0.102 maxpercent=80.000 minpercent=20.000
HoleToHoleClearance [All] p1: gap=0.203 allowstackedmicrovias=TRUE
MinimumAnnularRing MinimumAnnularRing_ThermalPadVias [IsVia and InAnyComponent] p1: minimumring=0.15
MinimumAnnularRing [All] p2: minimumring=0
MinimumSolderMaskSliver MinimumSolderMaskSliver_Logo [InComponentClass('Logo') vs InComponentClass('Logo')] p1: minsoldermaskwidth=0.018
MinimumSolderMaskSliver [All] p2: minsoldermaskwidth=0.1
PlaneConnect [All] p1: planeconnectstyle=Relief reliefexpansion=0.254 reliefentries=4 reliefconductorwidth=0.254 reliefairgap=0.254
PolygonConnect [All] p1: connectstyle=Direct reliefconductorwidth=0.254 reliefentries=4 polygonreliefangle="90 Angle" airgapwidth=0.254
RoutingVias ThermalPadVias [IsVia and InAnyComponent] p1: holewidth=0.2 width=0.5 viastyle="Through Hole" minholewidth=0.2 minwidth=0.5 maxholewidth=0.33 maxwidth=0.6
RoutingVias [All] p2: holewidth=0.406 width=0.864 viastyle="Through Hole" minholewidth=0.102 minwidth=0.203 maxholewidth=9 maxwidth=10
SilkToBoardRegionClearance [Not ((IsComment or IsDesignator) And (Hide <> 'False')) and not InRegion(1000,500,4000,800)] p1:
SilkToSilkClearance SilkToSilkClearance_Pb-FreeLogo [(HasFootprint('Pb-Free_Overlay_Medium') OR HasFootprint('Pb-Free_Overlay_Small')) vs (HasFootprint('Pb-Free_Overlay_Medium') OR HasFootprint('Pb-Free_Overlay_Small'))] p1: silktosilkclearance=0
SilkToSilkClearance [All] p2: silktosilkclearance=0.1
SilkToSolderMaskClearance SilkToComponentPadClearance [(IsPad or IsFill or IsRegion) and InAnycomponent] p1: minsilkscreentomaskgap=0.127 clearancetoexposedcopper=TRUE
SilkToSolderMaskClearance "Silk to Solder Mask Opening" [All] p2: minsilkscreentomaskgap=0.1 clearancetoexposedcopper=FALSE
SolderMaskExpansion [All] p1: expansion=0.05 istentingtop=FALSE
UnRoutedNet [All] p1: checkbadconnections=TRUE
Width [All] p1: maxlimit=2.54 minlimit=0.152 preferedwidth=0.254 substack1={36F540E3-592C-4459-9B98-FC5FBF0C6E90} checkconnectedcopper=TRUE
12 further rules are at their usual default settings.

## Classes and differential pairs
net class Secondary: BATT_RTN NetC321_1 NetC321_2 NetC353_1 NetC353_2 NetC356_2 NetC360_1 NetC360_2 NetC362_1 NetC362_2 NetC365_2 NetC377_1 NetFB301_2 NetFB302_2 NetFB304_2 NetFB305_2 NetR333_1 NetR345_2 NetR350_1 NetR351_2 NetR352_1 SGND VSNS_INN VSNS_INP
net class HV: DCLINK NetC324_1 NetC377_1 VBATT VBATT_F
component class "PMP23461 CLLLC Power Stage": C300 C301 C302 C303 C304 C305 C306 C307 C308 C309 C310 C311 C312 C313 C314 C315 C316 C317 C318 C320 C322 C323 C324 C325 C326 C369 C370 C371 C372 C373 C374 C375 C376 C377 C378 C379 C380 C381 C382 C383 C384 C385 C386 C387 C388 C389 C390 C391 C392 C393 C394 C395 C396 C397 C398 C399 C400 C401 C402 C403 C404 C405 C406 F300 F301 J300 J301 J302 J303 J304 J305 J306 J307 J308 LOGO300 LOGO301 LOGO302 LOGO303 R300 R301 R302 R303 R304 R305 R306 R307 R308 R309 R310 T300 T301 T302 TP300 TP301 TP302 TP303 TP304 TP305 TP306 TP307 TP308 TP309 TP310 TP311 TP312 TP313 TP314 TP315 TP316 TP317 TP318 TP319 TP320 TP321 TP322 TP323 TP324 TP325 TP326 TP327 TP328 TP330 TP331 TP332 TP333 TP334 U300
component class "PMP23461 CLLLC Sensing": C321 C327 C328 C329 C330 C331 C332 C333 C334 C335 C336 C337 C338 C339 C340 C341 C342 C343 C344 C345 C346 C347 C348 C349 C350 C351 C352 C353 C354 C355 C356 C357 C358 C359 C360 C361 C362 C363 C364 C365 C366 C367 C368 FB300 FB301 FB302 FB303 FB304 FB305 J309 J311 J313 R311 R312 R313 R314 R315 R316 R317 R318 R319 R320 R321 R322 R323 R324 R325 R326 R327 R328 R329 R330 R331 R332 R333 R334 R335 R336 R337 R338 R339 R340 R341 R342 R343 R344 R345 R346 R347 R348 R349 R350 R351 R352 R353 R354 R355 R356 R357 R358 R359 R360 R361 R362 U301 U302 U303 U304 U305 U306 U307 U308
net class HV_SW: SW_A SW_A_RES SW_A_XFMR SW_B SW_B_RES SW_C SW_C_RES SW_C_XFMR SW_D SW_D_RES

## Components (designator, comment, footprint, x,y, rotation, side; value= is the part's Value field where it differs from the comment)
C300 "AY2222M35Y5US63L7" AY2_950x500_Straight 119.428,124.051 r180 top value=2200pF
C301 "AY2222M35Y5US63L7" AY2_950x500_Straight 119.912,35.709 r180 top value=2200pF
C302 "C1210X333JBGACAUTO" FP-C1210X333JBGACAUTO_1210-MFG 75.797,58.28 r270 bottom value=33nF
C303 "C1210X333JBGACAUTO" FP-C1210X333JBGACAUTO_1210-MFG 167.929,62.582 r90 bottom value=33nF
C304 "C1210X333JBGACAUTO" FP-C1210X333JBGACAUTO_1210-MFG 79.658,58.28 r270 bottom value=33nF
C305 "C1210X333JBGACAUTO" FP-C1210X333JBGACAUTO_1210-MFG 164.494,62.582 r90 bottom value=33nF
C306 "C1210X333JBGACAUTO" FP-C1210X333JBGACAUTO_1210-MFG 75.777,58.305 r270 top value=33nF
C307 "C1210X333JBGACAUTO" FP-C1210X333JBGACAUTO_1210-MFG 164.563,62.489 r90 top value=33nF
C308 "C1210X333JBGACAUTO" FP-C1210X333JBGACAUTO_1210-MFG 79.638,58.305 r270 top value=33nF
C309 "C1210X333JBGACAUTO" FP-C1210X333JBGACAUTO_1210-MFG 167.998,62.489 r90 top value=33nF
C310 "C1210X333JBGACAUTO" FP-C1210X333JBGACAUTO_1210-MFG 76.511,111.063 r180 top value=33nF
C311 "C1210X333JBGACAUTO" FP-C1210X333JBGACAUTO_1210-MFG 162.524,109.629 r90 bottom value=33nF
C312 "C1210X333JBGACAUTO" FP-C1210X333JBGACAUTO_1210-MFG 76.511,114.619 r180 top value=33nF
C313 "C1210X333JBGACAUTO" FP-C1210X333JBGACAUTO_1210-MFG 166.121,109.684 r90 bottom value=33nF
C314 "C1210X333JBGACAUTO" FP-C1210X333JBGACAUTO_1210-MFG 76.511,114.618 r180 bottom value=33nF
C315 "C1210X333JBGACAUTO" FP-C1210X333JBGACAUTO_1210-MFG 166.121,109.675 r90 top value=33nF
C316 "C1210X333JBGACAUTO" FP-C1210X333JBGACAUTO_1210-MFG 76.511,111.063 r180 bottom value=33nF
C317 "C1210X333JBGACAUTO" FP-C1210X333JBGACAUTO_1210-MFG 162.519,109.642 r90 top value=33nF
C318 "04025U100CAT2A" 0402 12.267,107.417 r180 bottom value=10pF
C319 "ALA7DA471DE500" FP-ALA7DA471DE500_RADIAL-MFG 51.303,99.009 r180 top value=470µF
C320 "ALA7DA471DE500" FP-ALA7DA471DE500_RADIAL-MFG 51.236,62.227 r180 top value=470µF
C321 "C3216NP01H104J160AA" 1206_190 224.347,137.259 r270 bottom value=0.1uF
C322 "CGA2B3X7R1E104K050BB" 0402 110.53,121.578 r0 top value=0.1uF
C323 "ALA8DA301CF500" FP-ALA8DA301CF500_RADIAL-MFG 190.729,96.415 r180 top value=300µF
C324 "C1210X333JBGACAUTO" FP-C1210X333JBGACAUTO_1210-MFG 53.634,82.293 r0 bottom value=33nF
C325 "ALA8DA301CF500" FP-ALA8DA301CF500_RADIAL-MFG 190.624,64.564 r180 top value=300µF
C326 "C1210X333JBGACAUTO" FP-C1210X333JBGACAUTO_1210-MFG 53.634,79.118 r0 bottom value=33nF
C327 "CS0402KRX7R8BB104" 0402 122.789,149.57 r90 bottom value=0.1uF
C328 "04025U100CAT2A" 0402 12.302,106.096 r180 bottom value=10pF
C329 "C1005X7R1H222K050BE" 0402 119.944,146.39 r180 bottom value=2200pF
C330 "CGA2B3X7R1E104K050BB" 0402 116.236,150.667 r270 bottom value=0.1uF
C331 "04025U100CAT2A" 0402 120.503,153.126 r180 bottom value=10pF
C332 "CGA2B3X7R1H223K050BB" 0402 18.973,104.838 r0 bottom value=0.022uF
C333 "04025U100CAT2A" 0402 18.973,103.632 r0 bottom value=10pF
C334 "CGA2B3X7R1H103K050BB" 0402 184.521,152.756 r0 bottom value=0.01uF
C335 "CGA2B3X7R1E104K050BB" 0402 91.277,148.766 r90 bottom value=0.1uF
C336 "CGA2B3X7R1H103K050BB" 0402 189.186,149.378 r270 bottom value=0.01uF
C337 "CGA2B2X7R1H222K050BA" 0402 88.229,145.535 r180 bottom value=2200pF
C338 "CGA2B3X7R1E104K050BB" 0402 84.668,149.4 r270 bottom value=0.1uF
C339 "CGA2B3X7R1E104K050BB" 0402 183.499,146.457 r0 bottom value=0.1uF
C340 "04025U100CAT2A" 0402 88.432,153.257 r180 bottom value=10pF
C341 "CGA2B3X7R1H103K050BB" 0402 180.915,150.394 r270 bottom value=0.01uF
C342 "CGA2B3X7R1H223K050BB" 0402 17.068,108.949 r0 bottom value=0.022uF
C343 "CGA2B3X7R1H103K050BB" 0402 184.604,141.51 r270 bottom value=0.01uF
C344 "GCM155R71C104JA55D" 0402 19.116,96.926 r0 bottom value=0.1uF
C345 "GCM155R71H471KA37D" 0402 4.293,111.227 r180 bottom value=470pF
C346 "GCM155R71C104JA55D" 0402 18.973,107.086 r0 bottom value=0.1uF
C347 "CGA2B3X7R1H103K050BB" 0402 189.202,137.741 r270 bottom value=0.01uF
C348 "CGA2B3X7R1E104K050BB" 0402 183.301,134.896 r0 bottom value=0.1uF
C349 "CGA2B3X7R1E104K050BB" 0402 31.851,64.033 r90 top value=0.1uF
C350 "CGA2B3X7R1E104K050BB" 0402 6.968,106.528 r180 bottom value=0.1uF
C351 "CGA2B3X7R1H103K050BB" 0402 180.642,138.579 r270 bottom value=0.01uF
C352 "12065C102KAT2A" 1206 221.934,137.411 r270 bottom value=1000pF
C353 "CGA2B3X7R1H104K050BB" 0402 219.979,137.513 r90 bottom value=0.1uF
C354 "12065C102KAT2A" 1206 202.148,137.64 r270 bottom value=1000pF
C355 "12063C105KAT2A" 1206 204.864,137.654 r270 bottom value=1uF
C356 "C0603C104K5RACAUTO" 0603 224.068,142.237 r270 bottom value=0.1uF
C357 "C0603C104K5RACAUTO" 0603 205.271,144.092 r270 bottom value=0.1uF
C358 "CGA3E1X7R1E105K080AC" 0603S 220.436,143.863 r270 bottom value=1uF
C359 "C0603C102K5RACTU" 0603 222.417,143.888 r270 bottom value=1000pF
C360 "C3216NP01H104J160AA" 1206_190 224.347,149.705 r270 bottom value=0.1uF
C361 "12065C102KAT2A" 1206 221.909,149.654 r270 bottom value=1000pF
C362 "CGA2B2X7R1H102K050BA" 0402 219.928,149.502 r90 bottom value=1000pF
C363 "12065C102KAT2A" 1206 202.3,149.298 r270 bottom value=1000pF
C364 "12063C105KAT2A" 1206 204.991,149.35 r270 bottom value=1uF
C365 "C0603C104K5RACAUTO" 0603 223.662,154.201 r270 bottom value=0.1uF
C366 "C0603C104K5RACAUTO" 0603 205.475,155.902 r270 bottom value=0.1uF
C367 "CGA3E1X7R1E105K080AC" 0603S 220.334,155.648 r270 bottom value=1uF
C368 "C0603C102K5RACTU" 0603 221.934,155.623 r270 bottom value=1000pF
C369 "C1210X333JBGACAUTO" FP-C1210X333JBGACAUTO_1210-MFG 53.634,75.943 r0 bottom value=33nF
C370 "C1210X333JBGACAUTO" FP-C1210X333JBGACAUTO_1210-MFG 53.634,72.768 r0 bottom value=33nF
C371 "C1210X333JBGACAUTO" FP-C1210X333JBGACAUTO_1210-MFG 53.634,69.593 r0 bottom value=33nF
C372 "C1210X333JBGACAUTO" FP-C1210X333JBGACAUTO_1210-MFG 53.634,85.468 r0 bottom value=33nF
C373 "C1210X333JBGACAUTO" FP-C1210X333JBGACAUTO_1210-MFG 53.634,88.643 r0 bottom value=33nF
C374 "C1210X333JBGACAUTO" FP-C1210X333JBGACAUTO_1210-MFG 53.634,91.818 r0 bottom value=33nF
C375 "C1210X333JBGACAUTO" FP-C1210X333JBGACAUTO_1210-MFG 53.558,109.801 r0 bottom value=33nF
C376 "C1210X333JBGACAUTO" FP-C1210X333JBGACAUTO_1210-MFG 53.558,106.626 r0 bottom value=33nF
C377 "C1210X333JBGACAUTO" FP-C1210X333JBGACAUTO_1210-MFG 192.961,85.57 r0 bottom value=33nF
C378 "C1210X333JBGACAUTO" FP-C1210X333JBGACAUTO_1210-MFG 192.961,82.158 r0 bottom value=33nF
C379 "C1210X333JBGACAUTO" FP-C1210X333JBGACAUTO_1210-MFG 192.961,78.746 r0 bottom value=33nF
C380 "C1210X333JBGACAUTO" FP-C1210X333JBGACAUTO_1210-MFG 192.961,75.334 r0 bottom value=33nF
C381 "C1210X333JBGACAUTO" FP-C1210X333JBGACAUTO_1210-MFG 199.176,52.448 r45 bottom value=33nF
C382 "C1210X333JBGACAUTO" FP-C1210X333JBGACAUTO_1210-MFG 196.941,54.709 r45 bottom value=33nF
C383 "C1210X333JBGACAUTO" FP-C1210X333JBGACAUTO_1210-MFG 194.713,56.944 r45 bottom value=33nF
C384 "C1210X333JBGACAUTO" FP-C1210X333JBGACAUTO_1210-MFG 190.667,107.287 r45 bottom value=33nF
C385 "C1210X333JBGACAUTO" FP-C1210X333JBGACAUTO_1210-MFG 188.447,109.497 r45 bottom value=33nF
C386 "C1210X333JBGACAUTO" FP-C1210X333JBGACAUTO_1210-MFG 186.182,111.785 r45 bottom value=33nF
C387 "C1210X333JBGACAUTO" FP-C1210X333JBGACAUTO_1210-MFG 49.164,82.264 r0 bottom value=33nF
C388 "C1210X333JBGACAUTO" FP-C1210X333JBGACAUTO_1210-MFG 49.164,79.096 r0 bottom value=33nF
C389 "C1210X333JBGACAUTO" FP-C1210X333JBGACAUTO_1210-MFG 49.164,75.929 r0 bottom value=33nF
C390 "C1210X333JBGACAUTO" FP-C1210X333JBGACAUTO_1210-MFG 49.164,72.761 r0 bottom value=33nF
C391 "C1210X333JBGACAUTO" FP-C1210X333JBGACAUTO_1210-MFG 49.164,69.593 r0 bottom value=33nF
C392 "C1210X333JBGACAUTO" FP-C1210X333JBGACAUTO_1210-MFG 49.164,85.432 r0 bottom value=33nF
C393 "C1210X333JBGACAUTO" FP-C1210X333JBGACAUTO_1210-MFG 49.164,88.6 r0 bottom value=33nF
C394 "C1210X333JBGACAUTO" FP-C1210X333JBGACAUTO_1210-MFG 49.164,91.767 r0 bottom value=33nF
C395 "C1210X333JBGACAUTO" FP-C1210X333JBGACAUTO_1210-MFG 49.113,109.843 r0 bottom value=33nF
C396 "C1210X333JBGACAUTO" FP-C1210X333JBGACAUTO_1210-MFG 49.113,106.703 r0 bottom value=33nF
C397 "C1210X333JBGACAUTO" FP-C1210X333JBGACAUTO_1210-MFG 188.305,85.595 r0 bottom value=33nF
C398 "C1210X333JBGACAUTO" FP-C1210X333JBGACAUTO_1210-MFG 188.305,82.175 r0 bottom value=33nF
C399 "C1210X333JBGACAUTO" FP-C1210X333JBGACAUTO_1210-MFG 188.305,78.754 r0 bottom value=33nF
C400 "C1210X333JBGACAUTO" FP-C1210X333JBGACAUTO_1210-MFG 188.305,75.334 r0 bottom value=33nF
C401 "C1210X333JBGACAUTO" FP-C1210X333JBGACAUTO_1210-MFG 196.23,49.451 r45 bottom value=33nF
C402 "C1210X333JBGACAUTO" FP-C1210X333JBGACAUTO_1210-MFG 193.944,51.737 r45 bottom value=33nF
C403 "C1210X333JBGACAUTO" FP-C1210X333JBGACAUTO_1210-MFG 191.708,53.972 r45 bottom value=33nF
C404 "C1210X333JBGACAUTO" FP-C1210X333JBGACAUTO_1210-MFG 187.441,104.061 r45 bottom value=33nF
C405 "C1210X333JBGACAUTO" FP-C1210X333JBGACAUTO_1210-MFG 185.247,106.271 r45 bottom value=33nF
C406 "C1210X333JBGACAUTO" FP-C1210X333JBGACAUTO_1210-MFG 183.047,108.506 r45 bottom value=33nF
F300 "0525025.MXEP_vm" FP-0525025.MXEP_vm_AXIAL-MFG 219.105,95.044 r180 top
F301 "0525025.MXEP_vm" FP-0525025.MXEP_vm_AXIAL-MFG 213.535,103.299 r0 top
FB300 "MMZ1005Y182CTD25" FP-MMZ1005Y182CTD25_0402-MFG 225.211,132.534 r90 bottom
FB301 "MMZ1005Y182CTD25" FP-MMZ1005Y182CTD25_0402-MFG 226.633,132.534 r90 bottom
FB302 "MMZ1005Y182CTD25" FP-MMZ1005Y182CTD25_0402-MFG 228.03,132.534 r90 bottom
FB303 "MMZ1005Y182CTD25" FP-MMZ1005Y182CTD25_0402-MFG 225.744,145.387 r90 bottom
FB304 "MMZ1005Y182CTD25" FP-MMZ1005Y182CTD25_0402-MFG 227.167,145.387 r90 bottom
FB305 "MMZ1005Y182CTD25" FP-MMZ1005Y182CTD25_0402-MFG 228.538,145.412 r90 bottom
J300 "HLE-106-02-G-DV-BE-A" FP-HLE-106-02-G-DV-BE-A_HDR12-MFG 38.021,37.716 r0 bottom locked
J301 "HLE-106-02-G-DV-BE-A" FP-HLE-106-02-G-DV-BE-A_HDR12-MFG 142.643,37.716 r0 bottom locked
J302 "HLE-106-02-G-DV-BE-A" FP-HLE-106-02-G-DV-BE-A_HDR12-MFG 98.414,122.45 r180 bottom locked
J303 "HLE-106-02-G-DV-BE-A" FP-HLE-106-02-G-DV-BE-A_HDR12-MFG 209.463,122.273 r180 bottom locked
J304 "292161-2" FP-292161-2_HDR2-MFG 119.508,140.5 r0 top
J305 "74650074R" FP-74650074R_SCREW_MOUNTING-MFG 15.899,120.586 r0 bottom
J306 "74650074R" FP-74650074R_SCREW_MOUNTING-MFG 15.899,39.357 r180 bottom
J307 "74650074R" FP-74650074R_SCREW_MOUNTING-MFG 230.037,57.376 r90 bottom
J308 "74650074R" FP-74650074R_SCREW_MOUNTING-MFG 230.328,100.161 r0 bottom
J309 "LPPB102CFFN-RC" Sullins_LPPB102CFFN 15.677,79.972 r90 top
J311 "LPPB102CFFN-RC" Sullins_LPPB102CFFN 15.677,58.28 r90 top
J313 "LPPB102CFFN-RC" Sullins_LPPB102CFFN 15.677,101.663 r90 top
LOGO300 "DANGER HIGH VOLTAGE" IEC_HighVoltage_Small 212.587,37.157 r0 top
LOGO301 "DANGER HIGH VOLTAGE" IEC_HighVoltage_Small 85.663,152.08 r0 top
LOGO302 "CAUTION HOT SURFACE" IEC_HotSurface_Small 219.42,37.284 r0 top
LOGO303 "CAUTION HOT SURFACE" IEC_HotSurface_Small 93.166,152.171 r0 top
R300 "CRF1206-FZ-R010ELF" FP-CRF1206-FZ-R010ELF_1206-MFG 28.793,47.49 r0 bottom
R301 "WSL12066L000FEA18" 1206 216.573,54.757 r0 top value=0.006
R302 "CRF1206-FZ-R010ELF" FP-CRF1206-FZ-R010ELF_1206-MFG 28.793,47.49 r0 top
R303 "WSL12066L000FEA18" 1206 216.573,54.757 r0 bottom value=0.006
R304 "CRF1206-FZ-R010ELF" FP-CRF1206-FZ-R010ELF_1206-MFG 28.793,49.938 r0 top
R305 "WSL12066L000FEA18" 1206 216.573,57.438 r0 top value=0.006
R306 "CRF1206-FZ-R010ELF" FP-CRF1206-FZ-R010ELF_1206-MFG 28.793,52.387 r0 top
R307 "CRCW040256R2FKED" 0402 13.613,109.195 r180 bottom value=56.2
R308 "WSL12066L000FEA18" 1206 216.573,60.12 r0 bottom value=0.006
R309 "CRF1206-FZ-R010ELF" FP-CRF1206-FZ-R010ELF_1206-MFG 28.793,52.387 r0 bottom
R310 "WSL12066L000FEA18" 1206 216.573,60.12 r0 top value=0.006
R311 "ERJPA2F1002X" 0402 124.059,149.57 r270 bottom value=10.0k
R312 "CRCW04020000Z0ED" 0402 120.681,144.396 r90 bottom value=0
R313 "CRCW040256R2FKED" 0402 12.293,104.838 r0 bottom value=56.2
R314 "CRCW04021K00FKED" 0402 117.963,144.407 r90 bottom value=1.00k
R315 "CRCW04021K00FKED" 0402 117.986,147.144 r90 bottom value=1.00k
R316 "ERJPA2F1002X" 0402 121.346,147.614 r0 bottom value=10.0k
R317 "CRCW0402332RFKED" 0402 120.503,154.371 r0 bottom value=332
R318 "CRCW04028K45FKED" 0402 184.505,154 r0 bottom value=8.45k
R319 "ERJPA2F1002X" 0402 92.623,148.761 r270 bottom value=10.0k
R320 "CRCW04022K55FKED" 0402 191.185,150.063 r180 bottom value=2.55k
R321 "CRCW04022K55FKED" 0402 187.223,150.114 r180 bottom value=2.55k
R322 "CRCW04020000Z0ED" 0402 88.838,143.478 r90 bottom value=0
R323 "CRCW040211R0FKED" 0402 18.973,105.943 r180 bottom value=11.0
R324 "CRCW040256R2FKED" 0402 18.947,102.311 r180 bottom value=56.2
R325 "CRCW04022K55FKED" 0402 191.22,148.717 r180 bottom value=2.55k
R326 "CRCW04022K55FKED" 0402 187.188,148.768 r180 bottom value=2.55k
R327 "CRCW04021K00FKED" 0402 86.281,143.506 r90 bottom value=1.00k
R328 "CRCW04021K00FKED" 0402 86.298,146.221 r90 bottom value=1.00k
R329 "ERJPA2F1002X" 0402 89.6,146.78 r0 bottom value=10.0k
R330 "CRCW04023K65FKED" 0402 88.46,152.005 r0 bottom value=3.65k
R331 "CRCW04028K45FKED" 0402 179.67,150.394 r270 bottom value=8.45k
R332 "CRCW04020000Z0ED" 0402 234.863,142.364 r0 bottom value=0
R333 "ERJ-8ENF1242V" 1206 232.192,140.918 r90 bottom value=12.4k
R334 "CRCW04027K15FKED" 0402 185.874,141.535 r270 bottom value=7.15k
R335 "CRCW04020000Z0ED" 0402 234.812,139.316 r0 bottom value=0
R336 "ERJPA2F1002X" 0402 30.056,59.066 r90 top value=10.0k
R337 "CRCW04024K70JNED" 0402 191.208,138.427 r180 bottom value=4.7k
R338 "CRCW04024K70JNED" 0402 187.221,138.478 r180 bottom value=4.7k
R339 "CRCW06037K15FKEA" 0603 4.191,112.624 r180 bottom value=7.15k
R340 "CRCW04020000Z0ED" 0402 234.838,137.767 r0 bottom value=0
R341 "CRCW040211R0FKED" 0402 17.068,110.015 r180 bottom value=11.0
R342 "CRCW0402150KFKED" 0402 24.916,61.57 r0 top value=150k
R343 "CRCW04024K70JNED" 0402 191.208,137.03 r180 bottom value=4.7k
R344 "CRCW04024K70JNED" 0402 187.246,137.055 r180 bottom value=4.7k
R345 "CRCW12062M00FKEA" 1206 232.224,135.938 r270 bottom value=2.00Meg
R346 "CRCW040219R6FKED" 0402 18.414,94.98 r90 bottom value=19.6
R347 "CRCW040219R6FKED" 0402 9.83,109.83 r0 bottom value=19.6
R348 "ERJPA2F1002X" 0402 27.38,59.03 r270 top value=10.0k
R349 "CRCW04020000Z0ED" 0402 234.838,134.541 r0 bottom value=0
R350 "CRCW1206365KFKEA" 1206 7.188,113.919 r270 bottom value=365k
R351 "CRCW12062M00FKEA" 1206 232.224,130.909 r270 bottom value=2.00Meg
R352 "CRCW1206365KFKEA" 1206 7.188,118.821 r270 bottom value=365k
R353 "CRCW12062M00FKEA" 1206 232.224,125.88 r270 bottom value=2.00Meg
R354 "CRCW04027K15FKED" 0402 179.397,138.579 r90 bottom value=7.15k
R355 "CRCW1206365KFKEA" 1206 7.188,123.647 r270 bottom value=365k
R356 "CRCW0402150KFKED" 0402 27.948,65.644 r180 top value=150k
R357 "CRCW040239R2FKED" 0402 226.684,134.719 r90 bottom value=39.2
R358 "CRCW040239R2FKED" 0402 227.98,134.703 r90 bottom value=39.2
R359 "CRCW060347K0JNEA" 0603 204.459,140.916 r180 bottom value=47k
R360 "CRCW04020000Z0ED" 0402 227.141,147.626 r90 bottom value=0
R361 "CRCW04020000Z0ED" 0402 228.538,147.597 r90 bottom value=0
R362 "CRCW060347K0JNEA" 0603 204.713,152.651 r180 bottom value=47k
T300 "RLTI-1371" FP-RLTI-1371_PTH_XFRMR_0IN828_0IN300-MFG 81.128,101.854 r180 top
T301 "RLTI-1379" FP-RLTI-1379_PTH_XFRMR_0IN828_0IN300-MFG 162.712,98.692 r180 top
T302 "VT-20163" FP-VT-20163_PTH_TRANSFORMER_73MM0_51MM0-MFG 120.227,79.757 r180 top
TP300 "0312-0-15-15-34-27-10-0" Mill-Max_0312-0-15-15-34-27-10-0 64.691,34.742 r0 top locked
TP301 "0312-0-15-15-34-27-10-0" Mill-Max_0312-0-15-15-34-27-10-0 169.313,34.742 r0 top locked
TP302 "0312-0-15-15-34-27-10-0" Mill-Max_0312-0-15-15-34-27-10-0 59.611,34.742 r0 top locked
TP303 "0312-0-15-15-34-27-10-0" Mill-Max_0312-0-15-15-34-27-10-0 164.233,34.742 r0 top locked
TP304 "0312-0-15-15-34-27-10-0" Mill-Max_0312-0-15-15-34-27-10-0 72.311,34.742 r0 top locked
TP305 "0312-0-15-15-34-27-10-0" Mill-Max_0312-0-15-15-34-27-10-0 176.933,34.742 r0 top locked
TP306 "0312-0-15-15-34-27-10-0" Mill-Max_0312-0-15-15-34-27-10-0 77.391,34.742 r0 top locked
TP307 "0312-0-15-15-34-27-10-0" Mill-Max_0312-0-15-15-34-27-10-0 182.013,34.742 r0 top locked
TP308 "0312-0-15-15-34-27-10-0" Mill-Max_0312-0-15-15-34-27-10-0 90.091,34.742 r0 top locked
TP309 "0312-0-15-15-34-27-10-0" Mill-Max_0312-0-15-15-34-27-10-0 189.633,34.742 r0 top locked
TP310 "0312-0-15-15-34-27-10-0" Mill-Max_0312-0-15-15-34-27-10-0 85.011,34.742 r0 top locked
TP311 "0312-0-15-15-34-27-10-0" Mill-Max_0312-0-15-15-34-27-10-0 194.713,34.742 r0 top locked
TP312 "0312-0-15-15-34-27-10-0" Mill-Max_0312-0-15-15-34-27-10-0 76.824,125.424 r0 top locked
TP313 "0312-0-15-15-34-27-10-0" Mill-Max_0312-0-15-15-34-27-10-0 187.873,125.244 r0 top locked
TP314 "0312-0-15-15-34-27-10-0" Mill-Max_0312-0-15-15-34-27-10-0 71.744,125.424 r0 top locked
TP315 "0312-0-15-15-34-27-10-0" Mill-Max_0312-0-15-15-34-27-10-0 182.793,125.244 r0 top locked
TP316 "0312-0-15-15-34-27-10-0" Mill-Max_0312-0-15-15-34-27-10-0 59.044,125.424 r0 top locked
TP317 "0312-0-15-15-34-27-10-0" Mill-Max_0312-0-15-15-34-27-10-0 170.093,125.244 r0 top locked
TP318 "0312-0-15-15-34-27-10-0" Mill-Max_0312-0-15-15-34-27-10-0 64.124,125.424 r0 top locked
TP319 "0312-0-15-15-34-27-10-0" Mill-Max_0312-0-15-15-34-27-10-0 175.173,125.244 r0 top locked
TP320 "0312-0-15-15-34-27-10-0" Mill-Max_0312-0-15-15-34-27-10-0 51.424,125.424 r0 top locked
TP321 "0312-0-15-15-34-27-10-0" Mill-Max_0312-0-15-15-34-27-10-0 162.473,125.244 r0 top locked
TP322 "0312-0-15-15-34-27-10-0" Mill-Max_0312-0-15-15-34-27-10-0 46.344,125.424 r0 top locked
TP323 "0312-0-15-15-34-27-10-0" Mill-Max_0312-0-15-15-34-27-10-0 157.393,125.244 r0 top locked
TP324 "5001" Keystone5001 206.847,50.314 r90 top
TP325 "5001" Keystone5001 229.834,69.06 r90 top
TP326 "5000" Keystone5000 229.707,88.211 r90 top
TP327 "5001" Keystone5001 27.761,72.314 r90 top
TP328 "5001" Keystone5001 110.809,38.224 r90 top
TP329 "5001" Keystone5001 41.96,28.804 r90 top
TP330 "5001" Keystone5001 136.27,28.956 r90 top
TP331 "5001" Keystone5001 69.291,79.477 r90 top
TP332 "5001" Keystone5001 198.922,154.353 r90 top
TP333 "5001" Keystone5001 110.108,137.795 r90 top
TP334 "5001" Keystone5001 208.015,132.89 r90 top
U300 "TMP235AEDBZRQ1" DBZ0003A-MFG 110.903,118.911 r0 top
U301 "TLV365DBVRQ1" DBV0005A-MFG 119.517,150.317 r180 bottom
U302 "TLV365DBVRQ1" DBV0005A-MFG 87.645,149.421 r180 bottom
U303 "OPA320AQDBVRQ1" DBV0005A_N 183.794,149.53 r270 bottom
U304 "OPA320AQDBVRQ1" DBV0005A_N 183.538,137.792 r270 bottom
U305 "LMV796QMF/NOPB" DBV0005A_N 28.793,62.54 r0 top
U306 "OPA320AQDBVRQ1" DBV0005A_N 6.223,108.89 r0 bottom
U307 "AMC3302QDWERQ1" DWE0016A-MFG 213.019,140.053 r180 bottom
U308 "AMC3330QDWERQ1" DWE0016A-MFG 212.994,151.838 r180 bottom

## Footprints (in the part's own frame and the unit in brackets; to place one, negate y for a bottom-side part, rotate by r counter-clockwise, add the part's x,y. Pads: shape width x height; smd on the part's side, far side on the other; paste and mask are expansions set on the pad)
0402 [mm] "0402 from SM-752 data"
  rect 0.8x0.6 smd: 1(-0.6,0) 2(0.6,0)
  silkscreen extent -1.22,-0.52 1.22,0.52, body extent -0.55,-0.3 0.55,0.3, height 0.6
0603 [mm] "0603 from SM-752 data"
  rect 1x0.95 smd: 1(-0.8,0) 2(0.8,0)
  silkscreen extent -1.52,-0.69 1.52,0.69, body extent -0.87,-0.47 0.87,0.47, height 1
0603S [mil]
  rect 20x35 smd: 1(-30,0) 2(30,0)
  body extent -34,-19 34,19, height 39
1206 [mm] "1206 from SM-752 data"
  rect 1.3x1.85 smd: 1(-1.45,0) 2(1.45,0)
  silkscreen extent -2.4,-1.21 2.4,1.21, body extent -1.7,-0.9 1.7,0.9, height 1.35
1206_190 [mm] "1206_190"
  rect 1.1x1.6 smd: 1(-1.7,0) 2(1.7,0)
  silkscreen extent -0.9,-1 0.9,1, body extent -1.75,-0.95 1.75,0.95, height 1.9
AY2_950x500_Straight [mm] "TH, 2-Leads, 9.5x5mm, Pin Spacing 7.5mm"
  round 1.4 hole 0.9: 1(-3.75,1.6) 2(3.75,-1.6)
  silkscreen extent -4.75,-2.5 4.75,2.5, body extent -4.74,-2.5 4.75,2.5, height 12.5
DBV0005A-MFG [mm]
  rrect17% 1.1x0.6 smd paste+0 mask+0: 1(-1.3,0.95) 2(-1.3,0) 3(-1.3,-0.95) 4(1.3,-0.95) 5(1.3,0.95)
  silkscreen extent -2.53,-1.53 0.87,1.53, body extent -1.4,-1.45 1.4,1.45, height 1.45
DBV0005A_N [mm] "SOT23, 5-Leads, Body 2.9x1.6mm, Pitch 0.95mm, Lead Span 2.8mm, IPC Medium Density"
  rrect17% 1x0.6 smd: 1(-1.375,0.95) 2(-1.375,0) 3(-1.375,-0.95) 4(1.375,-0.95) 5(1.375,0.95)
  silkscreen extent -1.63,-1.55 0.38,1.55, body extent -1.42,-1.46 1.42,1.46, height 1.09
DBZ0003A-MFG [mm]
  rrect17% 1.3x0.6 smd paste+0 mask+0: 1(-1.05,0.95) 2(-1.05,-0.95) 3(1.05,0)
  silkscreen extent -0.7,-1.52 0.7,1.52, body extent -1.8,-1.62 1.8,1.62, height 0.25
DWE0016A-MFG [mm]
  rrect17% 1.65x0.6 smd paste+0 mask+0: 1(-4.875,4.445) 2(-4.875,3.175) 3(-4.875,1.905) 4(-4.875,0.635) 5(-4.875,-0.635) 6(-4.875,-1.905) 7(-4.875,-3.175) 8(-4.875,-4.445) 9(4.875,-4.445) 10(4.875,-3.175) 11(4.875,-1.905) 12(4.875,-0.635) 13(4.875,0.635) 14(4.875,1.905) 15(4.875,3.175) 16(4.875,4.445)
  silkscreen extent -6.38,-5.25 3.5,5.25, body extent -5.17,-5.15 5.17,5.15, height 2.65
FP-292161-2_HDR2-MFG [mm]
  rrect7% 1.35x1.35 hole 0.85 paste-1000 mask+0: 1(-1.3,0.2)
  round 1.35 hole 0.85 paste-1000 mask+0: 2(0.7,0.2)
  silkscreen extent -3,-1.9 3,1.9, body extent -3.1,-2 3.1,2, height 0.25
FP-0525025.MXEP_vm_AXIAL-MFG [mm]
  rrect5% 2.15x2.15 hole 1.4 paste-1000 mask+0: 1(0,0)
  round 2.15 hole 1.4 paste-1000 mask+0: 2(8.092,0)
  silkscreen extent -3.64,-3.64 3.64,3.64, body extent -3.74,-3.74 9.27,3.74, height 0.25
FP-74650074R_SCREW_MOUNTING-MFG [mm]
  round 3.2 hole 1.85 paste-1000 mask+0: 1(-2.935,-2.935) 1(-2.935,2.935) 1(2.935,-2.935) 1(2.935,2.935)
  round 4 hole 4 unplated paste-1000 mask+0: ""(0,0)
  silkscreen extent -5.67,-3.5 3.5,3.5, body extent -3.5,-3.5 3.5,3.5, height 3.1
FP-ALA7DA471DE500_RADIAL-MFG [mm]
  rrect3% 3.05x3.05 hole 2 paste-1000 mask+0: 1(-5,0)
  round 3.05 hole 2 paste-1000 mask+0: 2(5,0)
  silkscreen extent -18,-18 18,18, body extent -18.1,-18.1 18.1,18.1, height 0.25
FP-ALA8DA301CF500_RADIAL-MFG [mm]
  rrect3% 3.05x3.05 hole 2 paste-1000 mask+0: 1(-5,0)
  round 3.05 hole 2 paste-1000 mask+0: 2(5,0)
  silkscreen extent -15.5,-15.5 15.5,15.5, body extent -15.6,-15.6 15.6,15.6, height 0.25
FP-C1210X333JBGACAUTO_1210-MFG [mm]
  rrect8% 1.22x2.81 smd paste+0 mask+0: 1(-1.39,0) 2(1.39,0)
  silkscreen extent -0.41,-1.45 0.41,1.45, body extent -1.65,-1.3 1.65,1.3, height 2.8
FP-CRF1206-FZ-R010ELF_1206-MFG [mm]
  rrect6% 1.7x1.8 smd paste+0 mask+0: 1(-1.65,0) 2(1.65,0)
  silkscreen extent -0.43,-0.92 0.43,0.92, body extent -1.6,-0.83 1.6,0.82, height 0.8
FP-HLE-106-02-G-DV-BE-A_HDR12-MFG [mm]
  rrect8% 1.27x1.68 smd paste+0 mask+0: 1(6.35,-2.72) 2(6.35,2.72) 3(3.81,-2.72) 4(3.81,2.72) 5(1.27,-2.72) 6(1.27,2.72) 7(-1.27,-2.72) 8(-1.27,2.72) 9(-3.81,-2.72) 10(-3.81,2.72) 11(-6.35,-2.72) 12(-6.35,2.72)
  round 0.97 hole 0.97 unplated paste-1000 mask+0: ""(-6.35,-1.27) ""(-6.35,1.27) ""(-3.81,-1.27) ""(-3.81,1.27) ""(-1.27,-1.27) ""(-1.27,1.27) ""(1.27,-1.27) ""(1.27,1.27) ""(3.81,-1.27) ""(3.81,1.27) ""(6.35,-1.27) ""(6.35,1.27)
  round 1.78 hole 1.78 unplated paste-1000 mask+0: ""(-5.08,0) ""(5.08,0)
  silkscreen extent -7.72,-4.4 7.72,2.61, body extent -7.62,-3.29 7.62,3.29, height 3.79
FP-MMZ1005Y182CTD25_0402-MFG [mm]
  rrect20% 0.5x0.5 smd paste+0 mask+0: 1(-0.45,0) 2(0.45,0)
  silkscreen extent -0.53,-0.65 0.53,0.65, body extent -0.5,-0.25 0.5,0.25, height 0.55
FP-RLTI-1371_PTH_XFRMR_0IN828_0IN300-MFG [mm]
  rrect5% 2.05x2.05 hole 1.35 paste-1000 mask+0: 1(-6.604,-1.943)
  round 2.05 hole 1.35 paste-1000 mask+0: 2(-6.147,1.943) 3(6.147,1.943) 4(6.604,-1.943)
  silkscreen extent -10.71,-4.62 10.71,4, body extent -10.82,-4.1 10.82,4.1, height 0.25
FP-RLTI-1379_PTH_XFRMR_0IN828_0IN300-MFG [mm]
  rrect5% 2.05x2.05 hole 1.35 paste-1000 mask+0: 1(-6.604,-1.943)
  round 2.05 hole 1.35 paste-1000 mask+0: 2(-6.147,1.943) 3(6.147,1.943) 4(6.604,-1.943)
  silkscreen extent -10.71,-4.62 10.71,4, body extent -10.82,-4.1 10.82,4.1, height 0.25
FP-VT-20163_PTH_TRANSFORMER_73MM0_51MM0-MFG [mm]
  rrect5% 2.1x5.4 hole 4.8 slot 1.5 at 0 deg paste-1000 mask+0: 1(32.5,13)
  rrect100% 2.1x5.4 hole 4.8 slot 1.5 at 0 deg paste-1000 mask+0: 2(32.5,-13) 3(-37.5,-10) 4(-37.5,10)
  silkscreen extent -29.5,-30.5 34.62,30.5, body extent -41.37,-36.5 36.37,36.5, height 26.54
IEC_HighVoltage_Small [mm]
  silkscreen extent -2.72,-2.24 2.72,2.47
IEC_HotSurface_Small [mm]
  silkscreen extent -2.72,-2.36 2.72,2.35
Keystone5000 [mil] "For Keystone 500x miniature loop terminals"
  round 80 hole 40: 1(0,0)
  silkscreen extent -52,-52 52,52, body extent -49,-49 49,49, height 182
Keystone5001 [mil] "For Keystone 500x miniature loop terminals"
  round 80 hole 40: 1(0,0)
  silkscreen extent -52,-52 52,52, body extent -49,-49 49,49, height 182
Mill-Max_0312-0-15-15-34-27-10-0 [mm] "Pin Receptacle, .032-.046\" .075\" Dia, Gold, TH"
  round 2.45 hole 1.905: 1(0,0)
  silkscreen extent -1.52,-1.52 1.52,1.52, body extent -1.15,-1.15 1.16,1.15, height 0.46
Sullins_LPPB102CFFN [mm] "Receptacle, 1.27 mm, TH"
  rrect50% 0.9x0.9 hole 0.6: 1(-5.715,0.635)
  round 0.9 hole 0.6 mask+0.05: 2(-5.715,-0.635) 4(-4.445,-0.635) 6(-3.175,-0.635) 8(-1.905,-0.635) 10(-0.635,-0.635) 12(0.635,-0.635) 14(1.905,-0.635) 16(3.175,-0.635) 18(4.445,-0.635) 20(5.715,-0.635)
  round 0.9 hole 0.6: 3(-4.445,0.635) 5(-3.175,0.635) 7(-1.905,0.635) 9(-0.635,0.635) 11(0.635,0.635) 13(1.905,0.635) 15(3.175,0.635) 17(4.445,0.635) 19(5.715,0.635)
  body extent -6.55,-1.56 6.55,1.54, height 4.5

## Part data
C300 C301: library part CMP-0009587-2, "CAP, CERM, 2200 pF, 300 V, +/- 20%, Y5U, AEC-Q200 Grade 1, D9.5xT5mm", Cap_Case=9.5x5mm, Manufacturer=Vishay-Bccomponents, Supplier Part Number 1=BC2914-ND, TempCo=Y5U, Tolerance_%=20%, Value1=Unknown, Value2=300V, ValueDisplayed=2200pF
C302 C303 C304 C305 C306 C307 C308 C309 C310 C311 C312 C313 C314 C315 C316 C317 C324 C326 C369 C370 C371 C372 C373 C374 C375 C376 C377 C378 C379 C380 C381 C382 C383 C384 C385 C386 C387 C388 C389 C390 C391 C392 C393 C394 C395 C396 C397 C398 C399 C400 C401 C402 C403 C404 C405 C406: library part CMP-0090696-1, "0.033µF ±5% 630V Ceramic Capacitor C0G, NP0 1210 (3225 Metric)", Digikey Part Number=399-20933-1-ND, Manufacturer=Kemet, Mouser Part Number=80-C1210X333JBGAUTO, Operating Temperature Range="-55°C to +125°C", TempCo=30ppm/°C, Temperature Characteristic=C0G, Tolerance_%=5%, ValueDisplayed=0.033uF
C318 C328 C331 C333 C340: library part CMP-0064911-2, "CAP, CERM, 10 pF, 50 V,+/- 2.5%, C0G/NP0, AEC-Q200 Grade 1, 0402", Cap_Case=0402, Manufacturer=AVX, Supplier Part Number 1=478-5991-1-ND, TempCo=C0G/NP0, Tolerance_%=2.5%, Value1=Unknown, Value2=50V, ValueDisplayed=10pF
